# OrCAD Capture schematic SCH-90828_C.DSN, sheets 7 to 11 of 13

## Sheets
7 07 AUDIO: size C; note: SCH-90828 PDF: SPF-90828
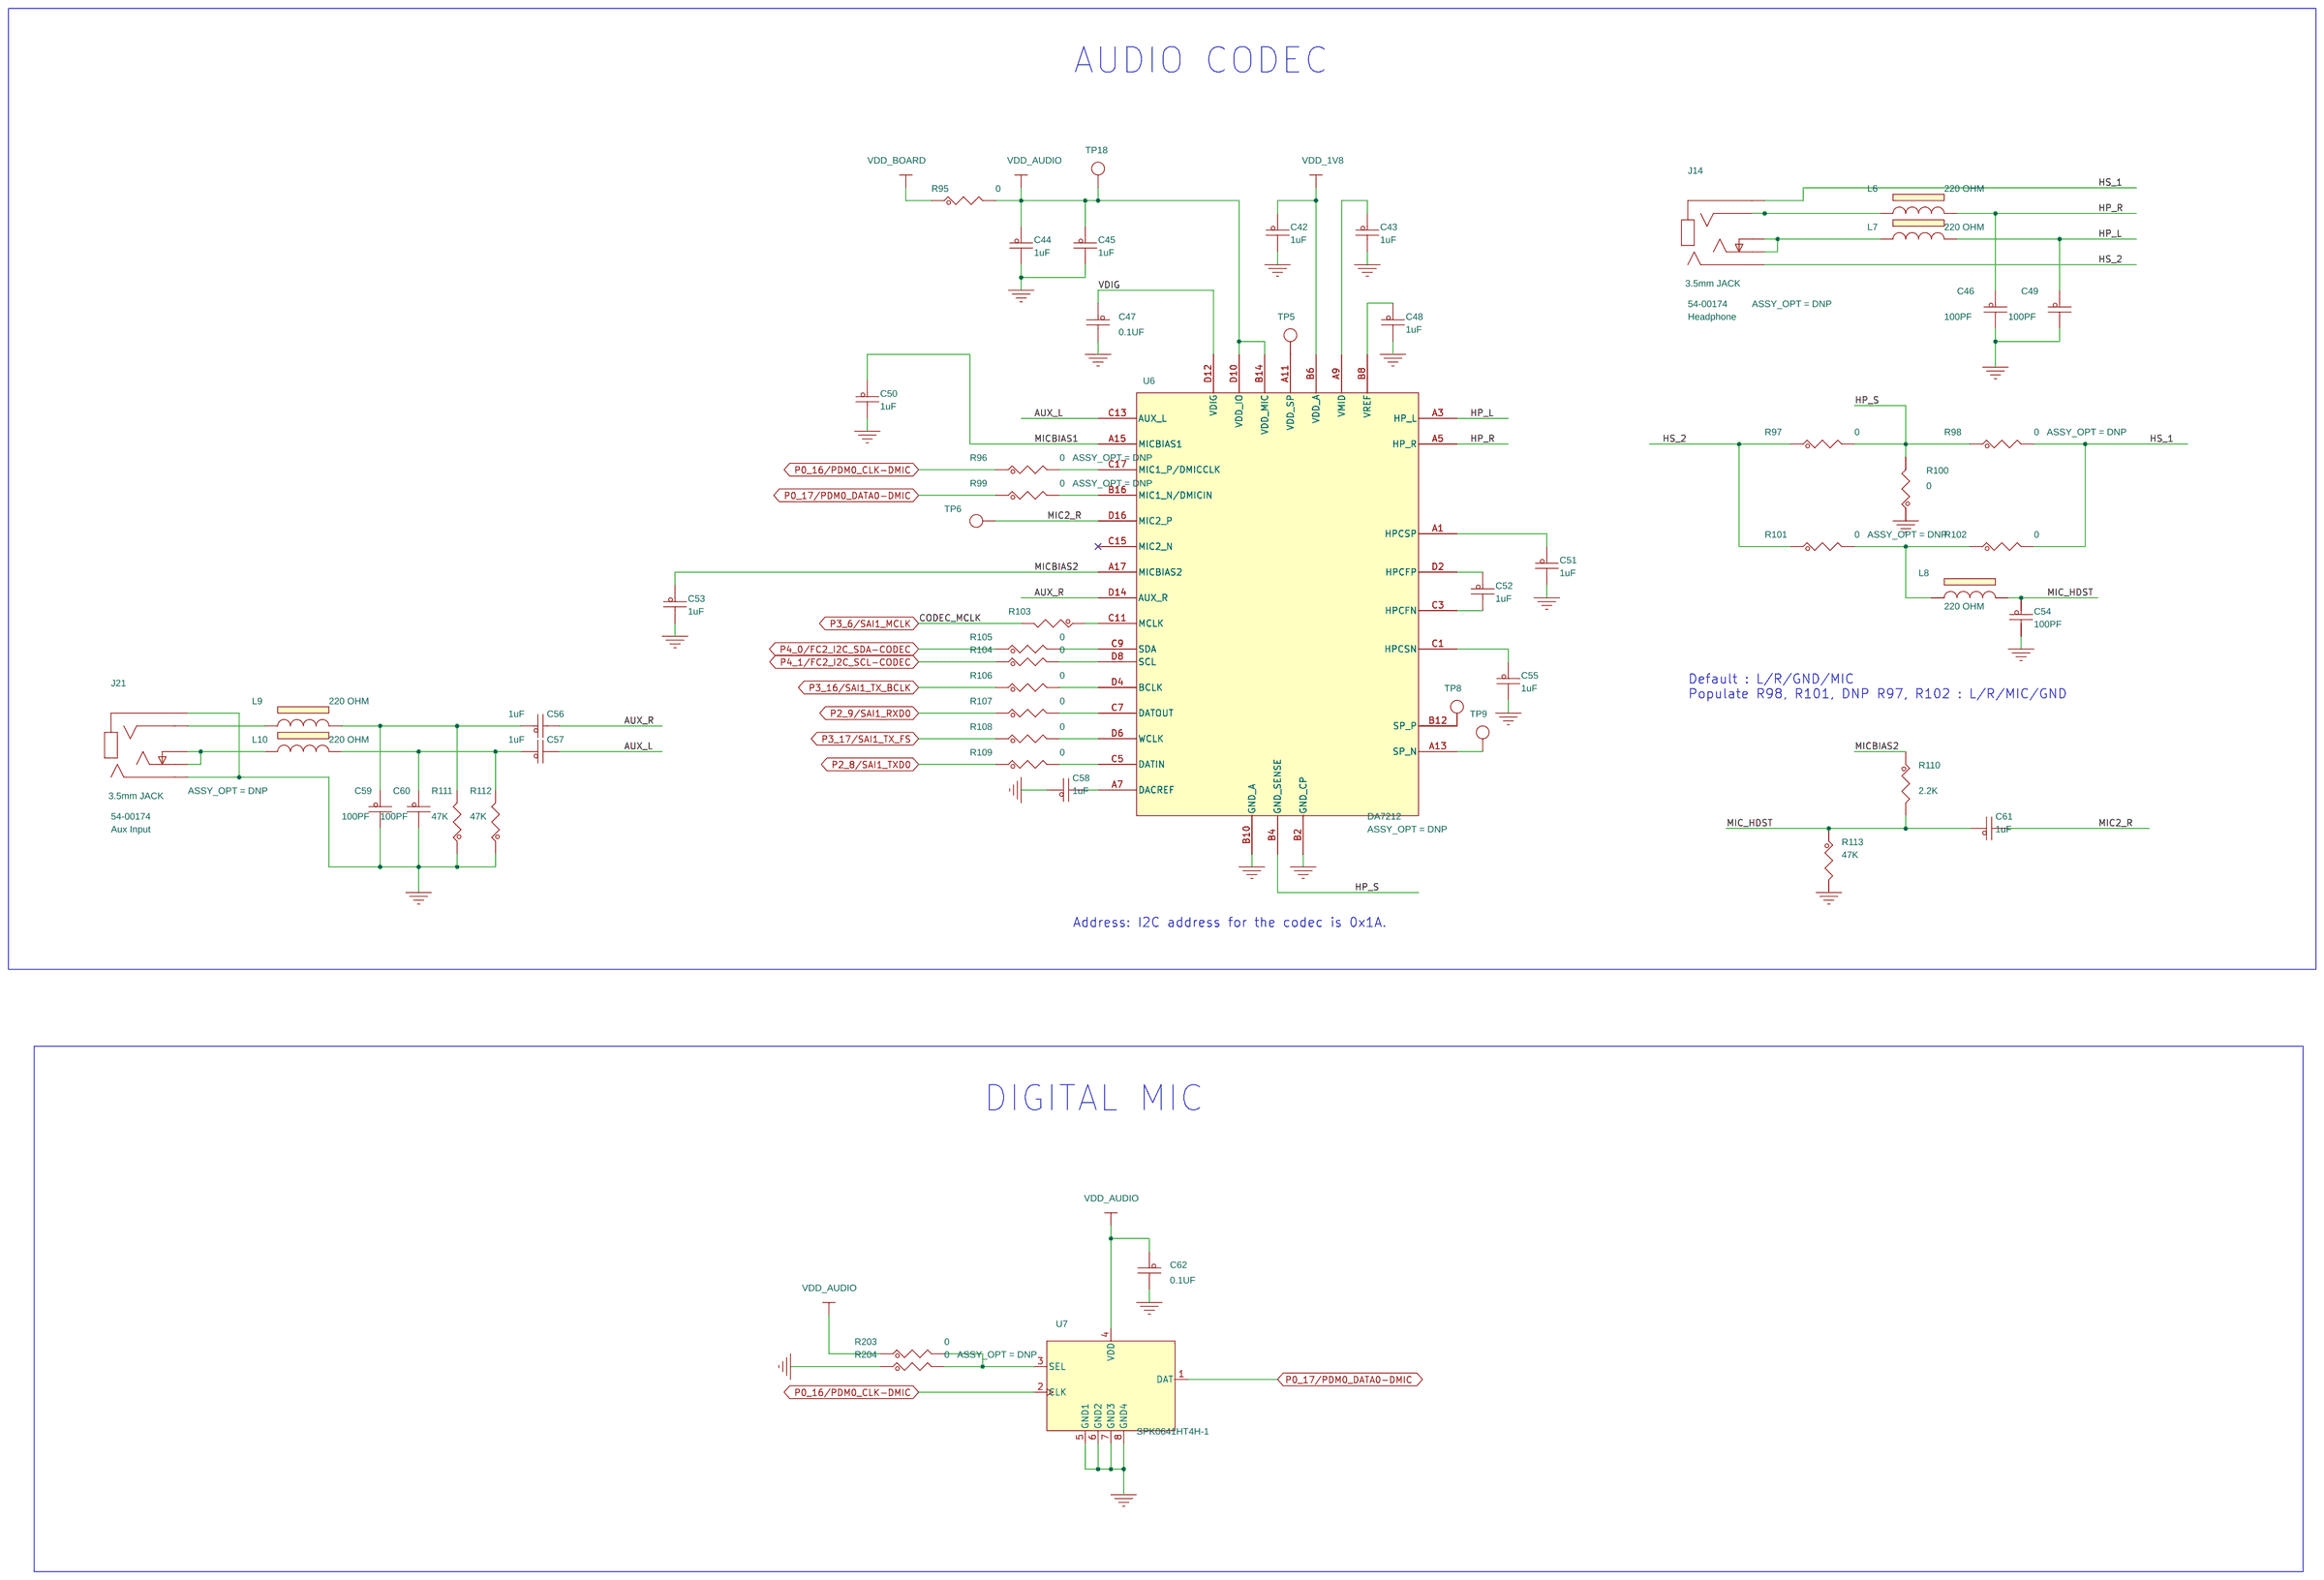
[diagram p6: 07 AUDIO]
8 08 MCU_LINK_USB: size C; note: SCH-90828 PDF: SPF-90828
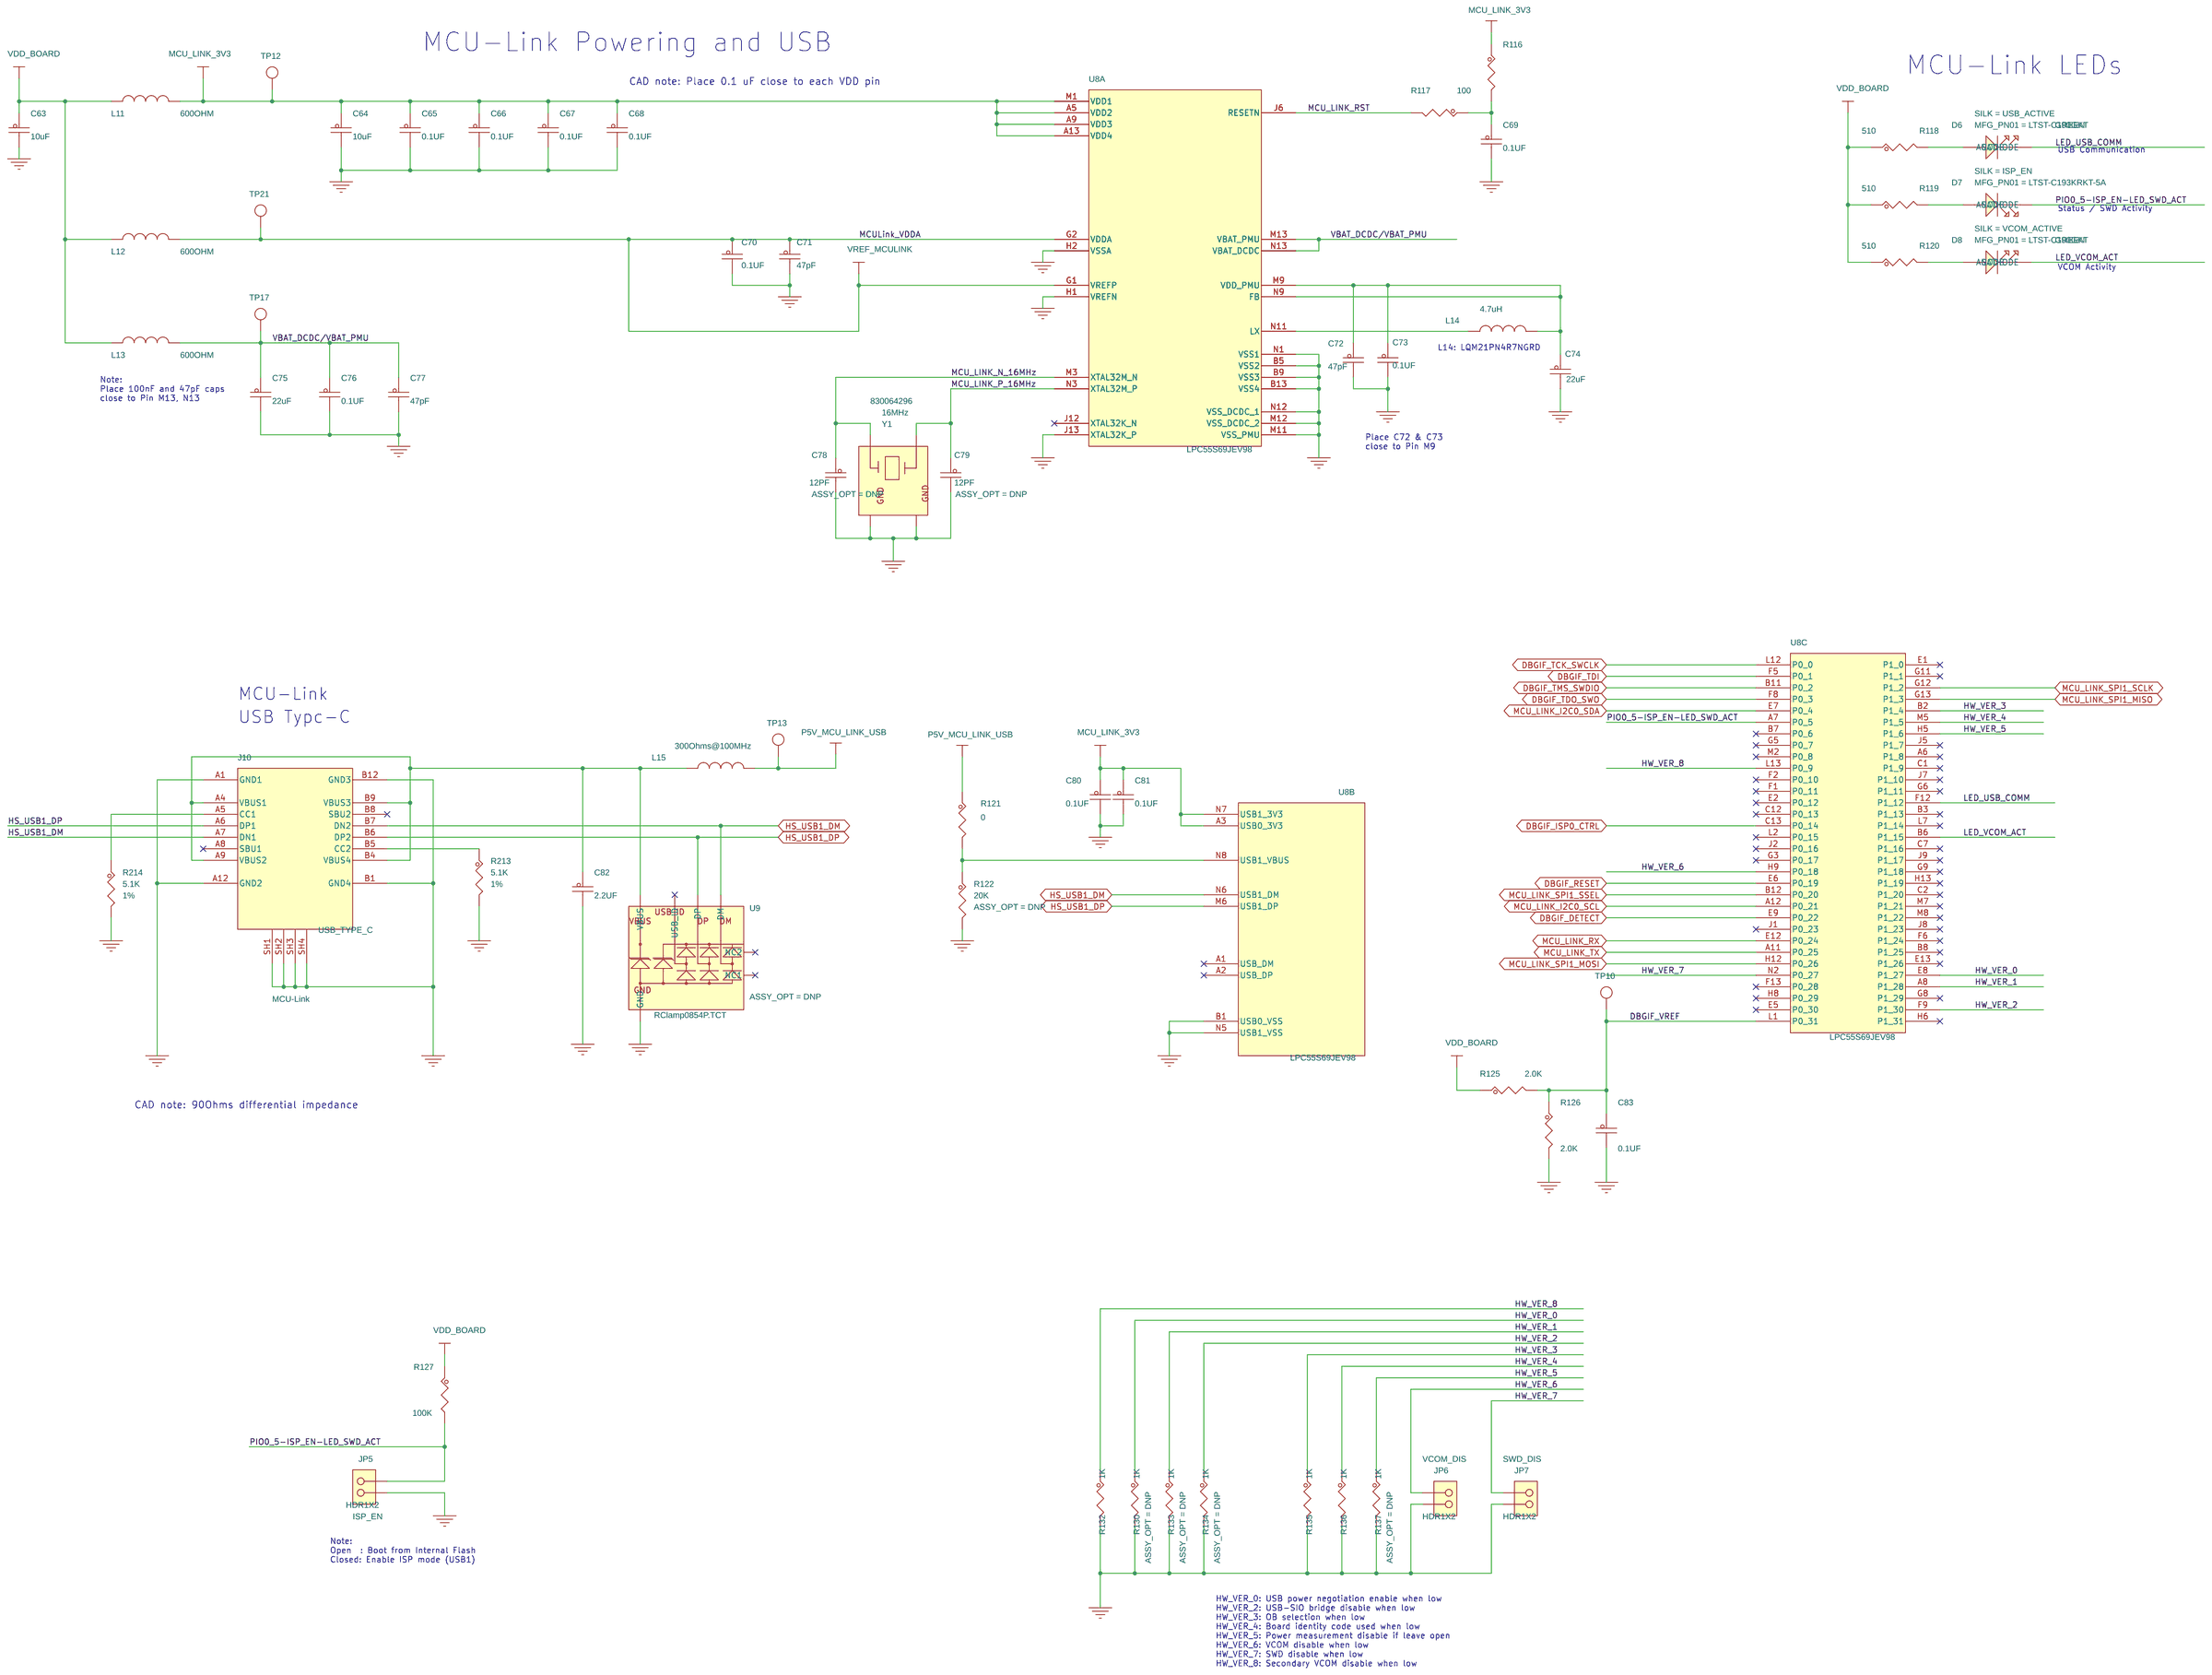
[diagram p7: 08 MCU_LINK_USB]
9 09 MCU_LINK_DEBUG: size C; note: SCH-90828 PDF: SPF-90828
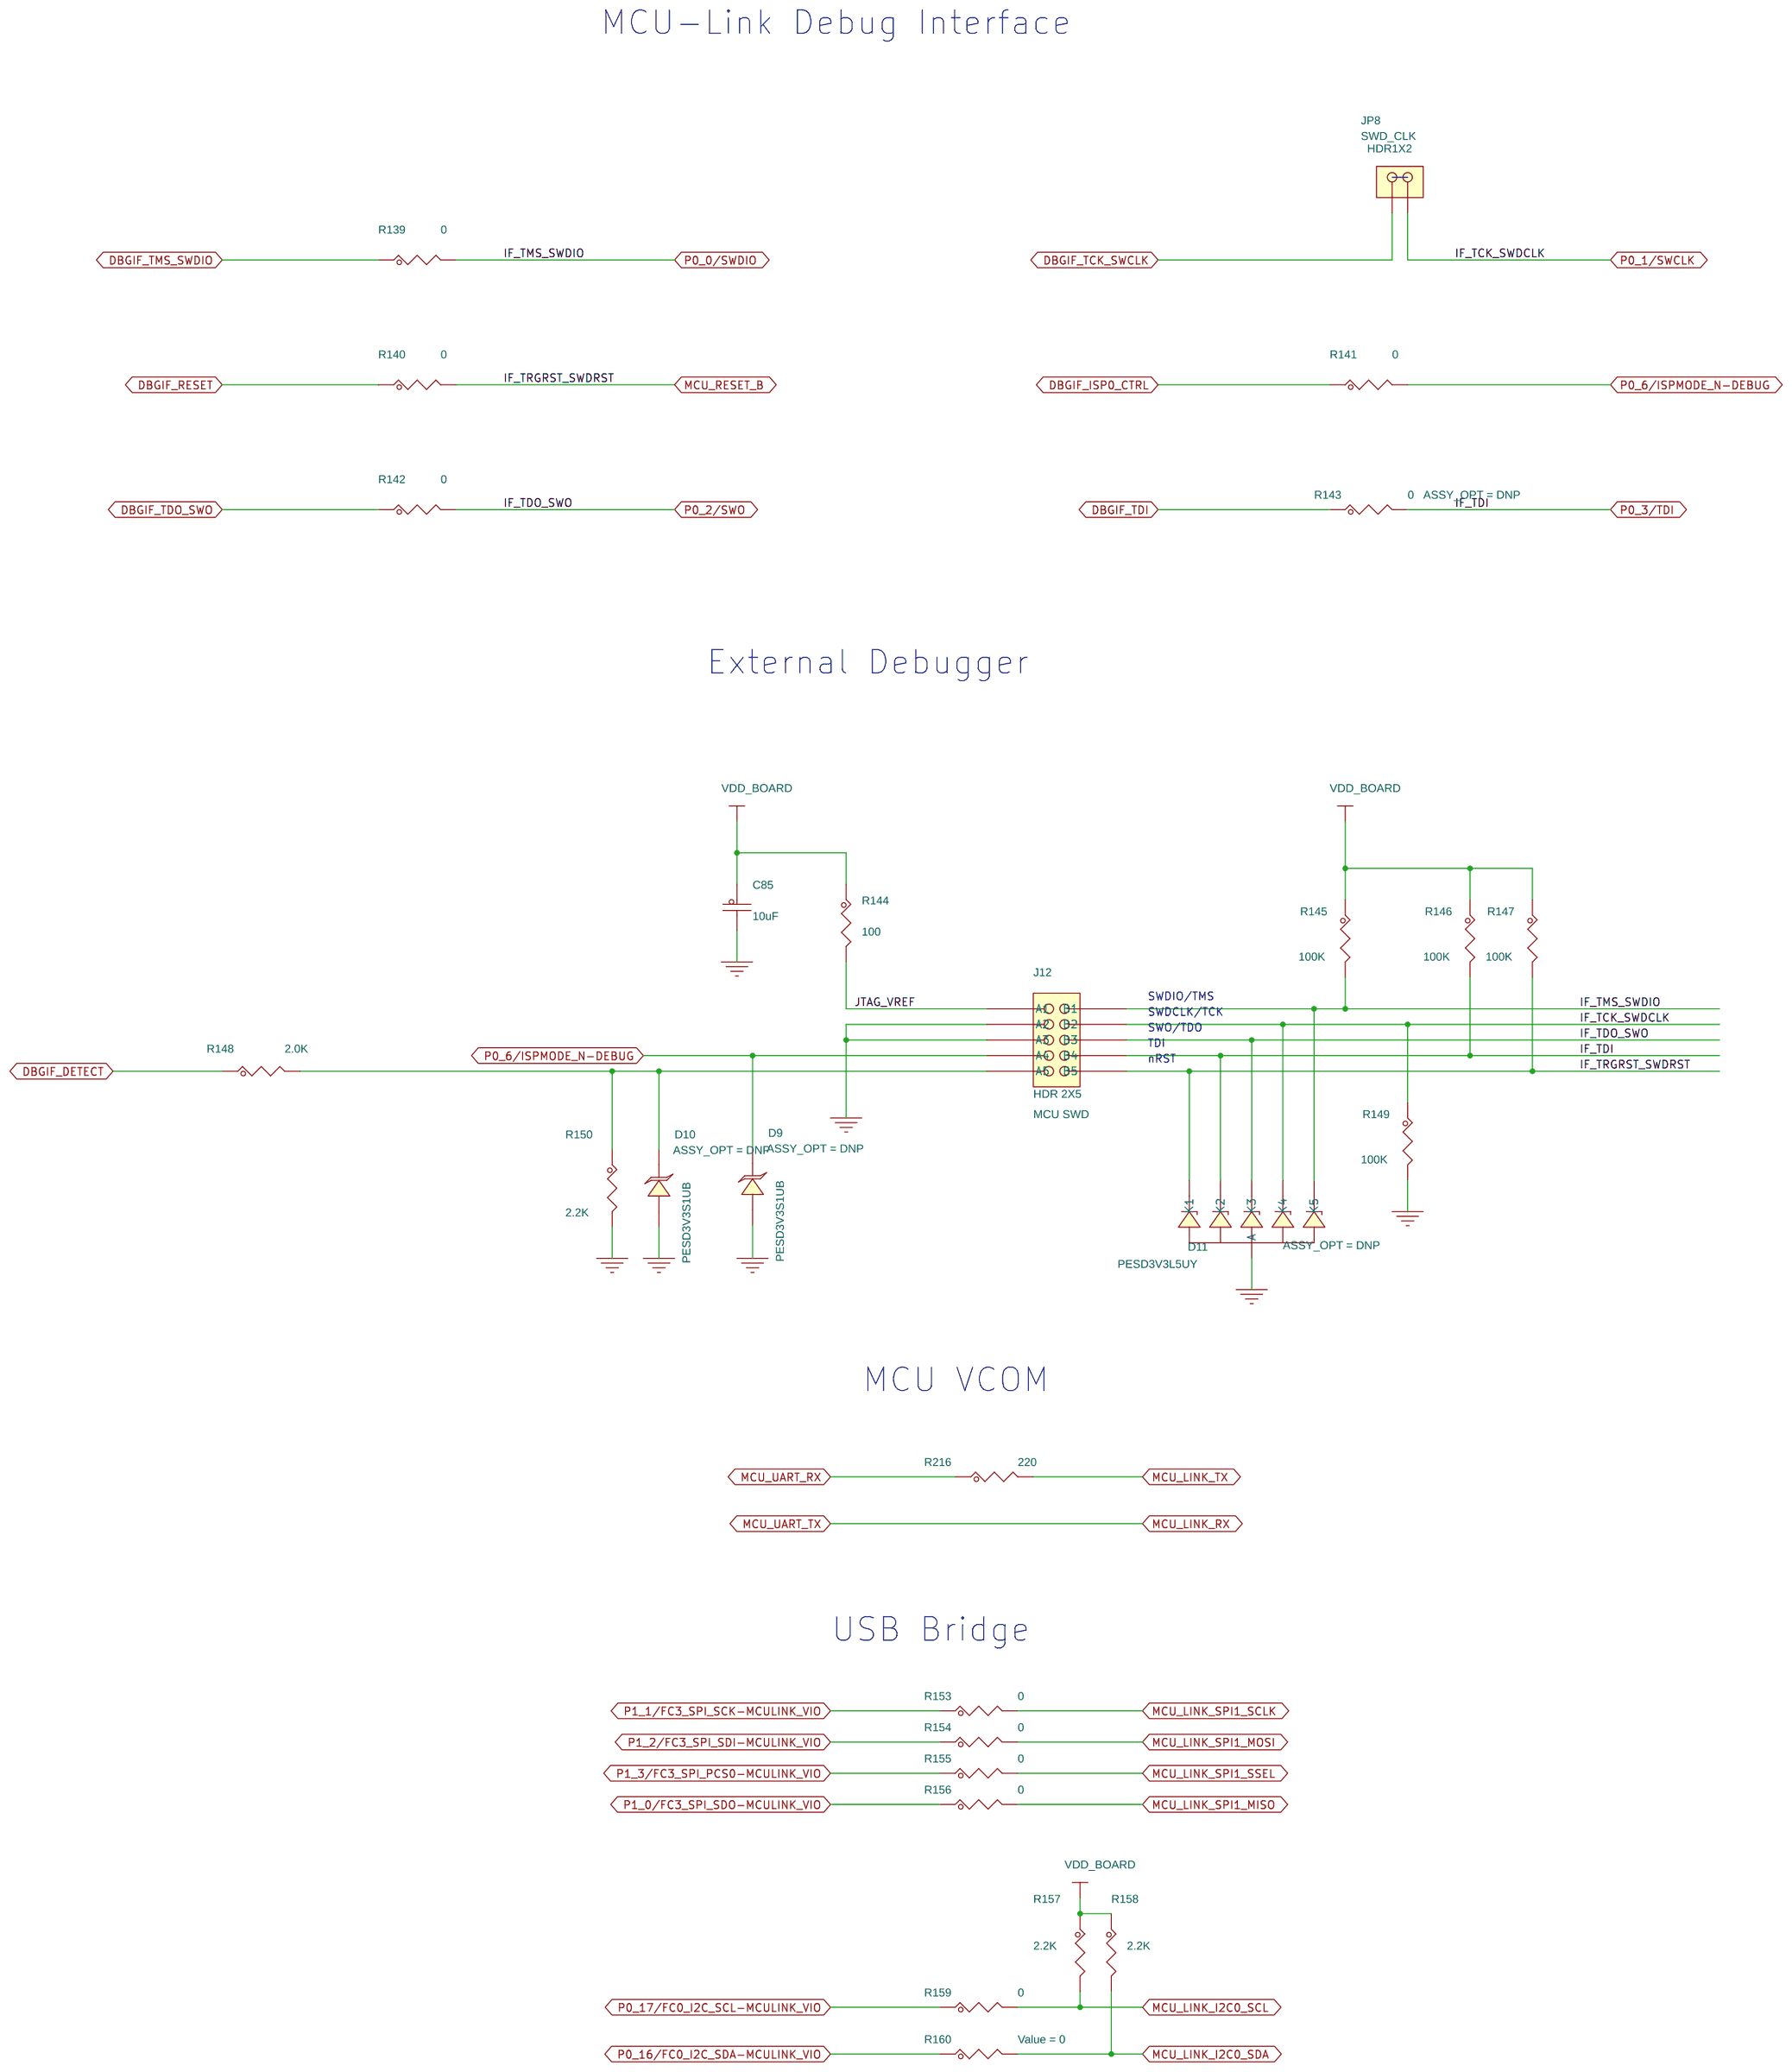
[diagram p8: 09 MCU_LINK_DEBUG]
10 10 CLOCK_RESET_HMI: size C; note: SCH-90828 PDF: SPF-90828
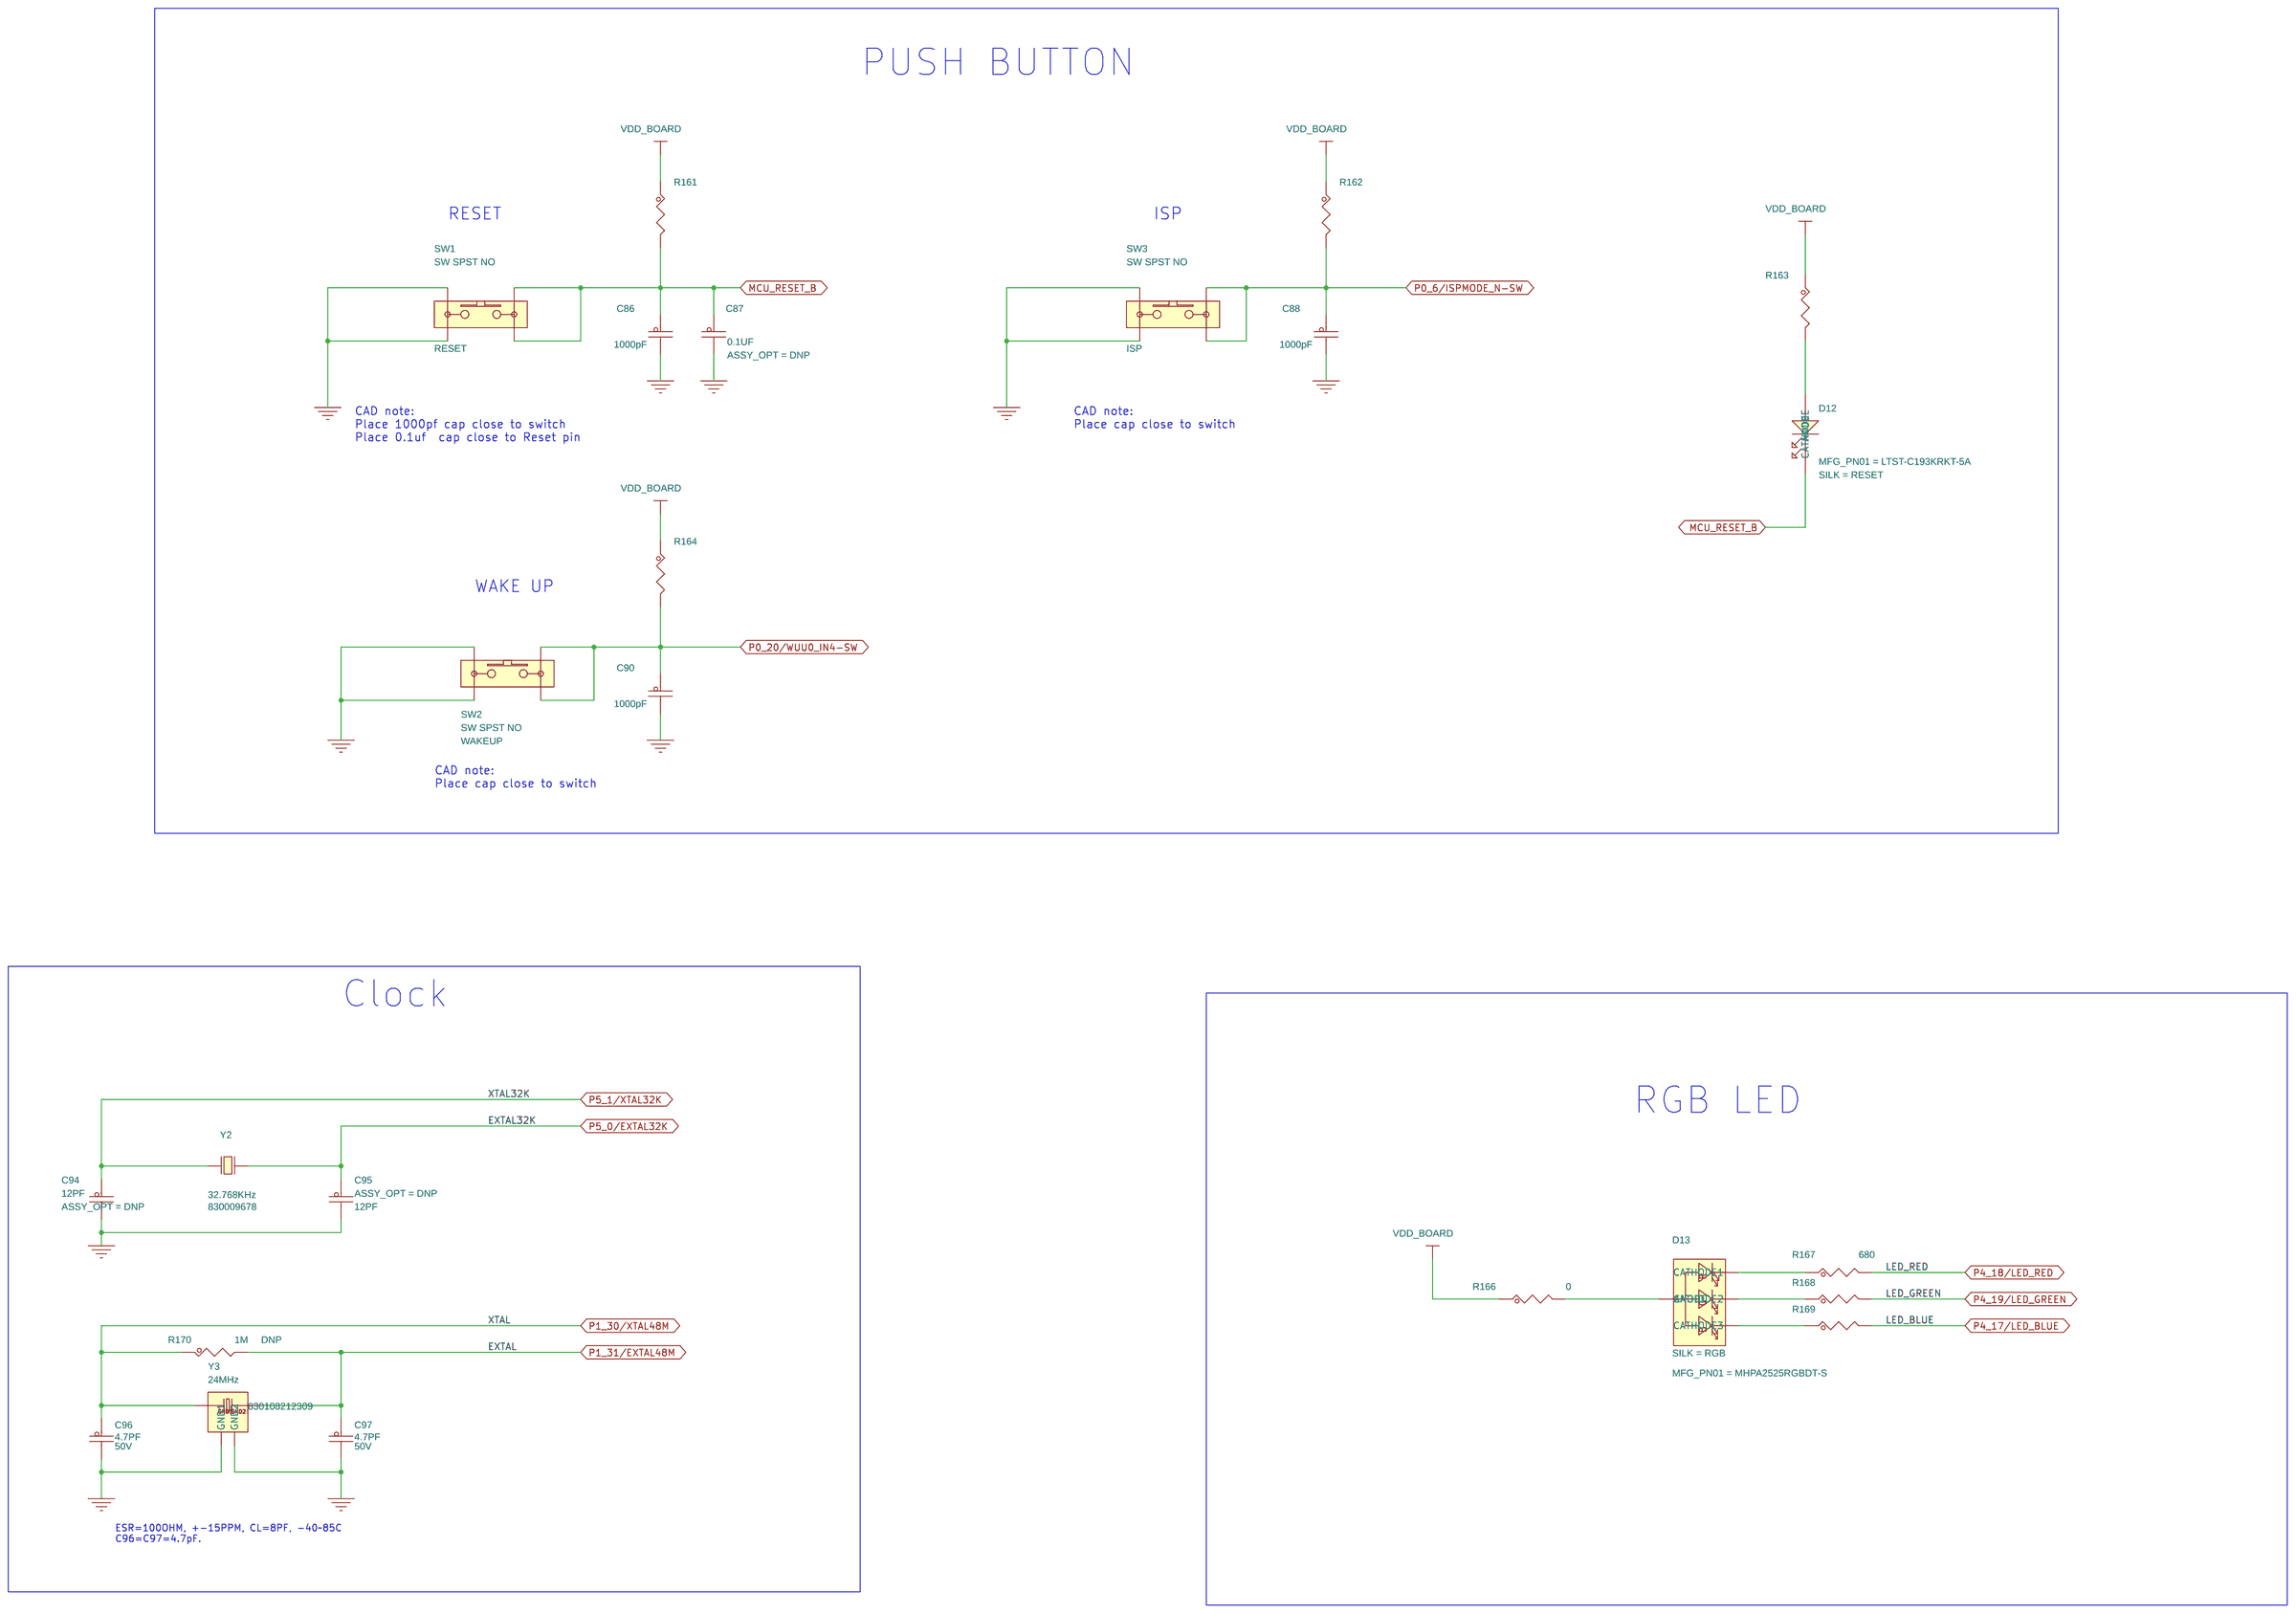
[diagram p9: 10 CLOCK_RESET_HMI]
11 11 SENSOR_CAN_QSPI: size C; note: SCH-90828 PDF: SPF-90828
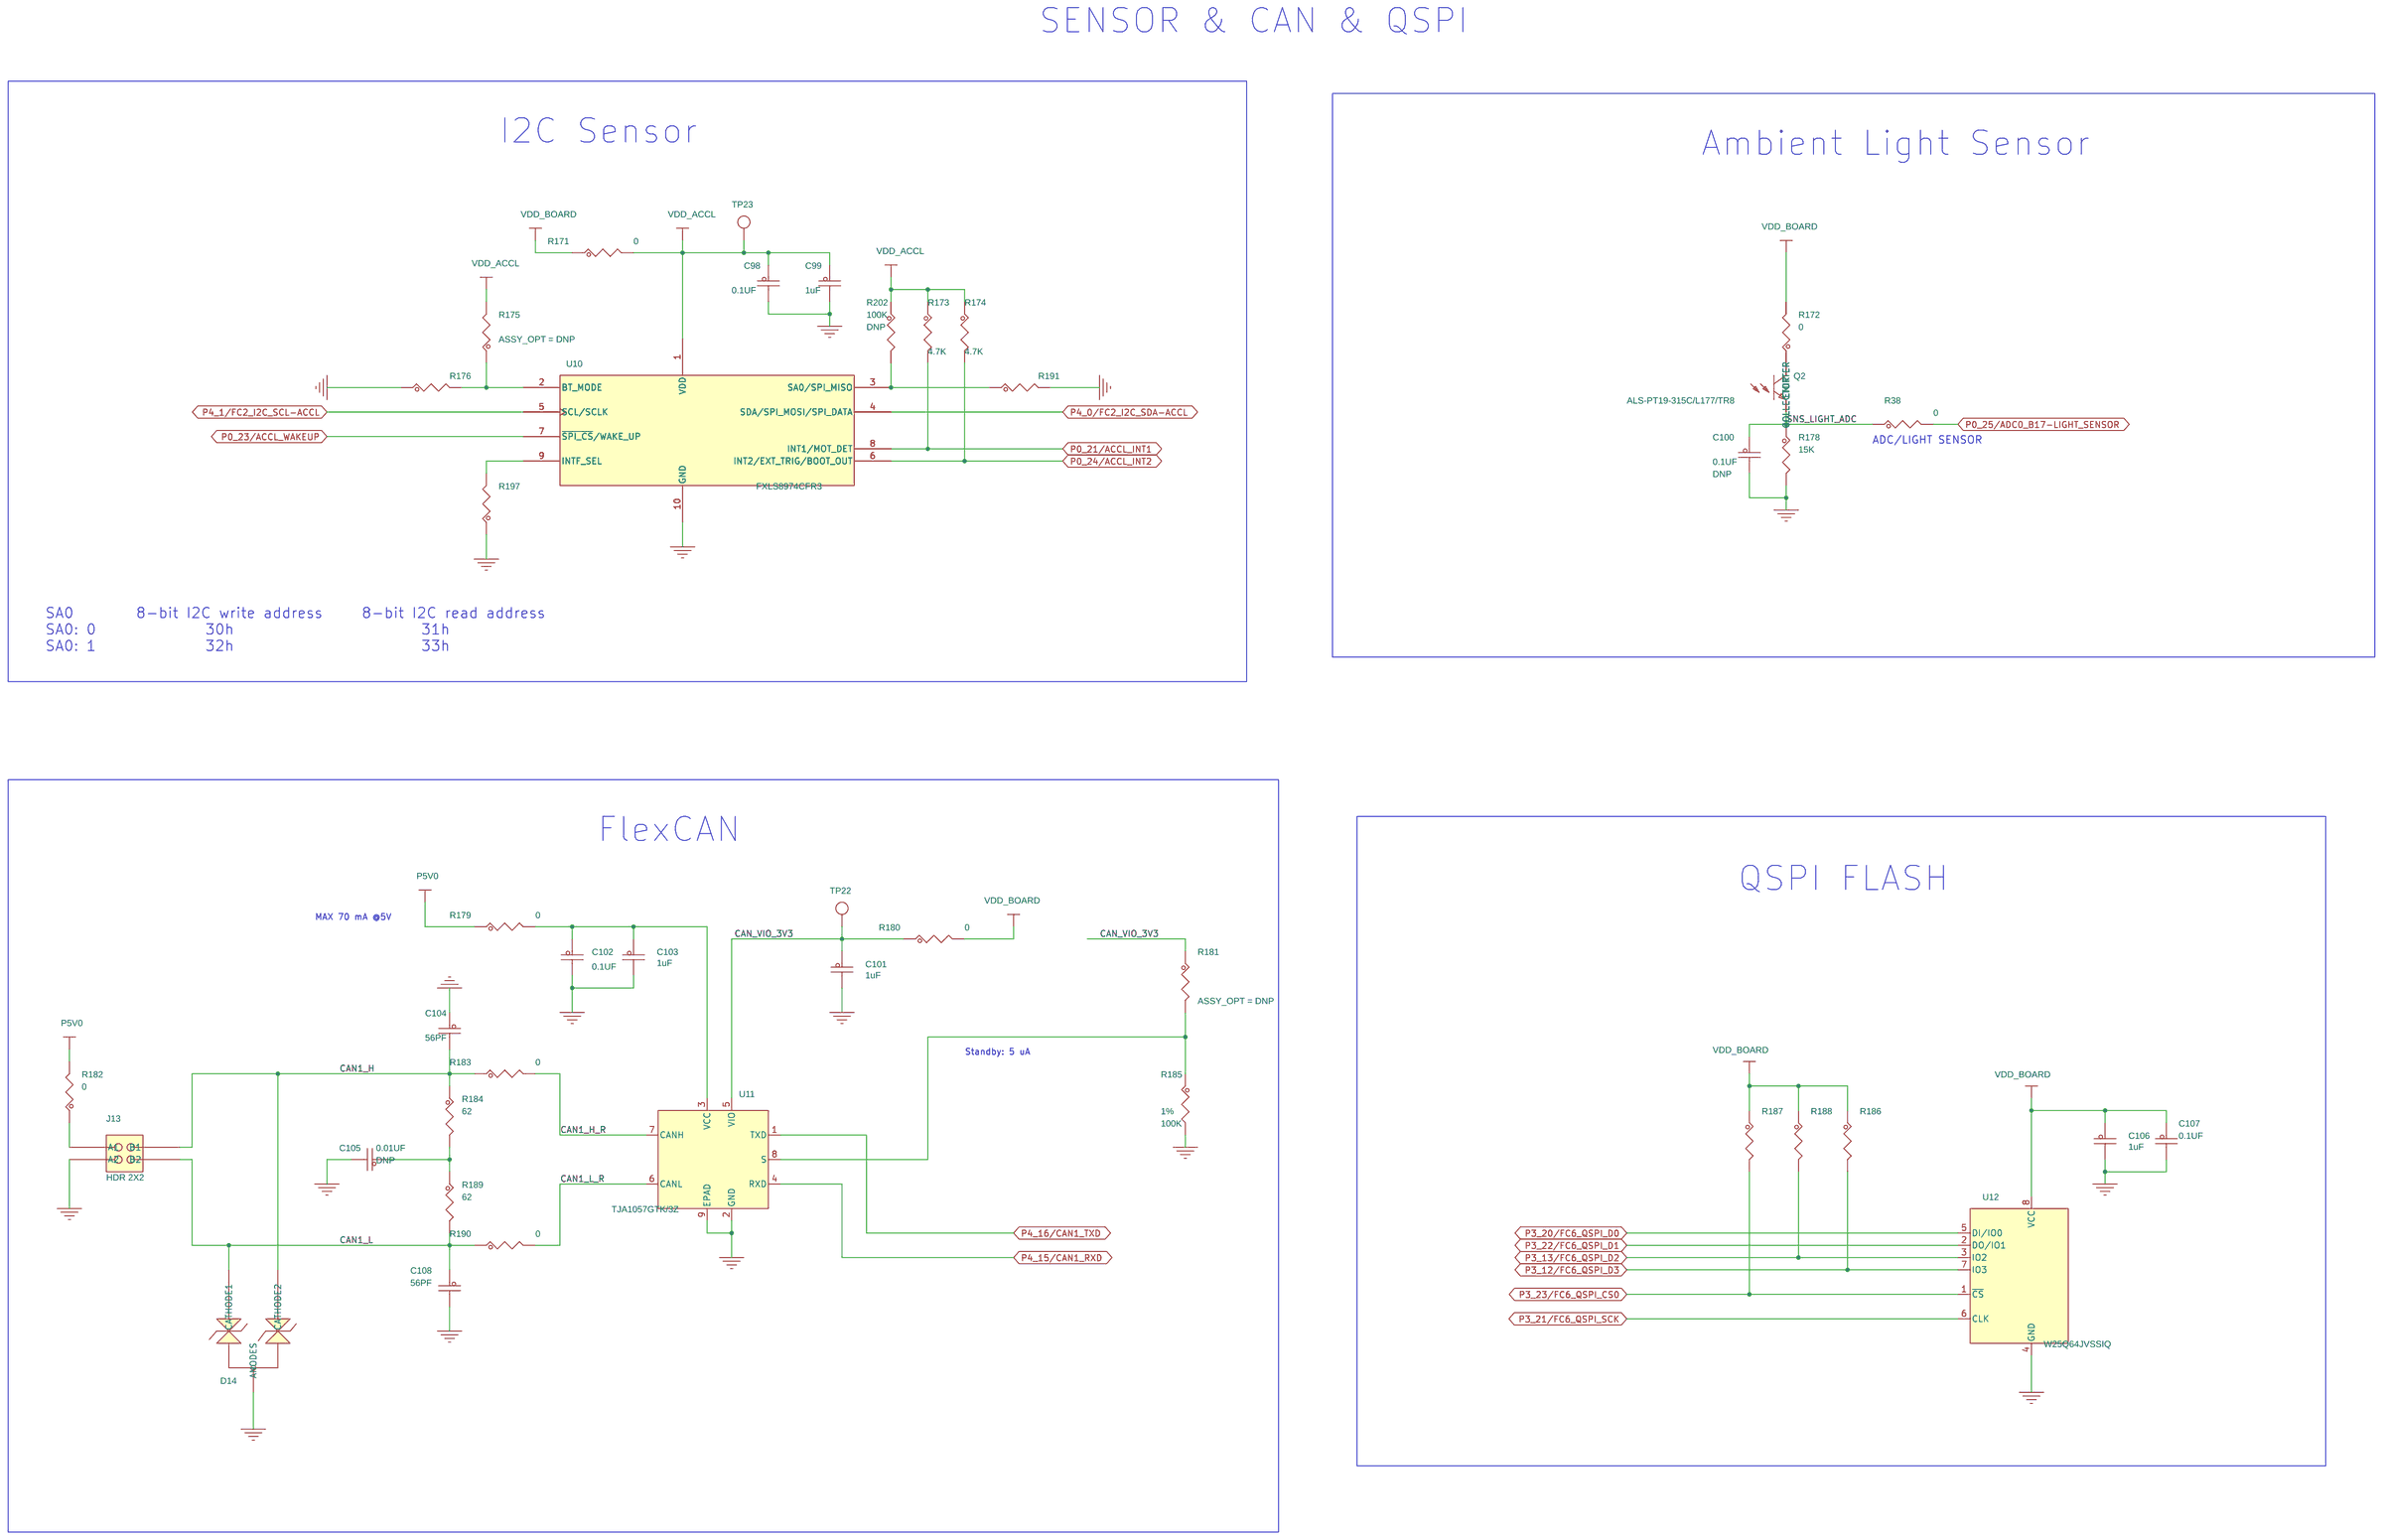
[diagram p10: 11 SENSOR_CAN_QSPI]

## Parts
sheet 07 AUDIO
C42  1uF  [CC0402_25]
C43  1uF  [CC0402_25]
C44  1uF  [CC0402_25]
C45  1uF  [CC0402_25]
C46  100PF  [CC0402_25]
C47  0.1UF  [CC0402_25]
C48  1uF  [CC0402_25]
C49  100PF  [CC0402_25]
C50  1uF  [CC0402_25]
C51  1uF  [CC0402_25]
C52  1uF  [CC0402_25]
C53  1uF  [CC0402_25]
C54  100PF  [CC0402_25]
C55  1uF  [CC0402_25]
C56  1uF  [CC0402_25]
C57  1uF  [CC0402_25]
C58  1uF  [CC0402_25]
C59  100PF  [CC0402_25]
C60  100PF  [CC0402_25]
C61  1uF  [CC0402_25]
C62  0.1UF  [CC0402_25]
J14  3.5mm JACK  [con5_jack_ra_th]
J21  3.5mm JACK  [con5_jack_ra_th]
L6  220 OHM  [IND_0402]
L7  220 OHM  [IND_0402]
L8  220 OHM  [IND_0402]
L9  220 OHM  [IND_0402]
L10  220 OHM  [IND_0402]
R95  0  [RC0402_25]
R96  0  [RC0402_25]
R97  0  [RC0402_25]
R98  0  [RC0402_25]
R99  0  [RC0402_25]
R100  0  [RC0402_25]
R101  0  [RC0402_25]
R102  0  [RC0402_25]
R103  33  [RC0402_25]
R104  0  [RC0402_25]
R105  0  [RC0402_25]
R106  0  [RC0402_25]
R107  0  [RC0402_25]
R108  0  [RC0402_25]
R109  0  [RC0402_25]
R110  2.2K  [RC0402_25]
R111  47K  [RC0402_25]
R112  47K  [RC0402_25]
R113  47K  [RC0402_25]
R203  0  [RC0402_25]
R204  0  [RC0402_25]
TP5  TPAD_040  [TPAD_040]
TP6  TPAD_040  [TPAD_040]
TP8  TPAD_040  [TPAD_040]
TP9  TPAD_040  [TPAD_040]
TP18  TPAD_040  [TPAD_040]
U6  DA7212  [csp34_0p5_4p54x1p66]
U7  SPK0641HT4H-1  [lga8_3p1x4p1mm_spk0641]
sheet 08 MCU_LINK_USB
C63  10uF  [CC0603_OV]
C64  10uF  [CC0603_OV]
C65  0.1UF  [CC0402_25]
C66  0.1UF  [CC0402_25]
C67  0.1UF  [CC0402_25]
C68  0.1UF  [CC0402_25]
C69  0.1UF  [CC0402_25]
C70  0.1UF  [CC0402_25]
C71  47pF  [CC0603_OV]
C72  47pF  [CC0603_OV]
C73  0.1UF  [CC0402_25]
C74  22uF  [CC0603_OV]
C75  22uF  [CC0603_OV]
C76  0.1UF  [CC0402_25]
C77  47pF  [CC0603_OV]
C78  12PF  [0402_CC]
C79  12PF  [0402_CC]
C80  0.1UF  [CC0402_25]
C81  0.1UF  [CC0402_25]
C82  2.2UF  [CC0402_25]
C83  0.1UF  [CC0402_25]
D6  GREEN  [LED_0603]
D7  RED  [LED_0603]
D8  GREEN  [LED_0603]
J10  USB_TYPE_C  [con16_usb_type-c_ra_th]
JP5  HDR1X2  [hdr1x2_5p48x2p69]
JP6  HDR1X2  [hdr1x2_5p48x2p69]
JP7  HDR1X2  [hdr1x2_5p48x2p69]
L11  600OHM  [ind_1p8x1mm_sm]
L12  600OHM  [ind_1p8x1mm_sm]
L13  600OHM  [ind_1p8x1mm_sm]
L14  4.7uH  [IND_0805]
L15  300Ohms@100MHz  [ind_1p8x1mm_sm]
R116  10K  [RC0402_25]
R117  100  [RC0402_25]
R118  510  [RC0402_25]
R119  510  [RC0402_25]
R120  510  [RC0402_25]
R121  0  [RC0402_25]
R122  20K  [RC0402_25]
R125  2.0K  [RC0603_OV]
R126  2.0K  [RC0603_OV]
R127  100K  [RC0402_25]
R130  1K  [rc0402_25]
R132  1K  [rc0402_25]
R133  1K  [rc0402_25]
R134  1K  [rc0402_25]
R135  1K  [rc0402_25]
R136  1K  [rc0402_25]
R137  1K  [rc0402_25]
R213  5.1K  [RC0402_25]
R214  5.1K  [RC0402_25]
TP10  TPAD_040  [TPAD_040]
TP12  TPAD_040  [TPAD_040]
TP13  TPAD_040  [TPAD_040]
TP17  TPAD_040  [TPAD_040]
TP21  TPAD_040  [TPAD_040]
U8  LPC55S69JEV98  [bga98_0p5_7x7]  (sections A,B,C)
U9  RClamp0854P.TCT  [slp1616p6]
Y1  16MHz  [xtal4_3p4x2p7_sm]
sheet 09 MCU_LINK_DEBUG
C85  10uF  [CC0603_OV]
D9  PESD3V3S1UB  [sod523]
D10  PESD3V3S1UB  [sod523]
D11  PESD3V3L5UY  [sot-363_0p65_smt]
J12  HDR 2X5  [hdr_5X2_ftsh_th]
JP8  HDR1X2  [hdr1x2_5p48x2p69]
R139  0  [RC0402_25]
R140  0  [RC0402_25]
R141  0  [RC0402_25]
R142  0  [RC0402_25]
R143  0  [RC0402_25]
R144  100  [RC0402_25]
R145  100K  [RC0402_25]
R146  100K  [RC0402_25]
R147  100K  [RC0402_25]
R148  2.0K  [RC0603_OV]
R149  100K  [RC0402_25]
R150  2.2K  [RC0402_25]
R153  0  [RC0402_25]
R154  0  [RC0402_25]
R155  0  [RC0402_25]
R156  0  [RC0402_25]
R157  2.2K  [RC0402_25]
R158  2.2K  [RC0402_25]
R159  0  [RC0402_25]
R160  0  [RC0402_25]
R216  220  [RC0603_OV]
sheet 10 CLOCK_RESET_HMI
C86  1000pF  [CC0402_25]
C87  0.1UF  [CC0402_25]
C88  1000pF  [CC0402_25]
C90  1000pF  [CC0402_25]
C94  12PF  [CC0402_25]
C95  12PF  [CC0402_25]
C96  4.7PF  [0402_CC]
C97  4.7PF  [0402_CC]
D12  RED  [LED_0603]
D13  RGB  [led4_2p7x2p6_sm]
R161  10K  [RC0402_25]
R162  10K  [RC0402_25]
R163  470  [RC0402_25]
R164  10K  [RC0402_25]
R166  0  [RC0402_25]
R167  680  [RC0603_OV]
R168  470  [RC0402_25]
R169  470  [RC0402_25]
R170  1M  [0402_CC]
SW1  SW SPST NO  [sw4_4p15_4p2x3p2_sm]
SW2  SW SPST NO  [sw4_4p15_4p2x3p2_sm]
SW3  SW SPST NO  [sw4_4p15_4p2x3p2_sm]
Y2  32.768KHz  [XTAL2-3p2x1p5-SM]
Y3  24MHz  [xtal4_2p1x1p7mm_sm]
sheet 11 SENSOR_CAN_QSPI
C98  0.1UF  [CC0402_25]
C99  1uF  [CC0402_25]
C100  0.1UF  [CC0402_25]
C101  1uF  [CC0402_25]
C102  0.1UF  [CC0402_25]
C103  1uF  [CC0402_25]
C104  56PF  [CC0402_25]
C105  0.01UF  [CC0402_25]
C106  1uF  [CC0402_25]
C107  0.1UF  [CC0402_25]
C108  56PF  [CC0402_25]
D14  NUP2105L  [sot-23]
J13  HDR 2X2  [hdr202_100_th]
Q2  ALS-PT19-315C/L177/TR8  [phtrans_1p9x1]
R38  0  [RC0402_25]
R171  0  [RC0402_25]
R172  0  [RC0402_25]
R173  4.7K  [RC0402_25]
R174  4.7K  [RC0402_25]
R175  10K  [RC0402_25]
R176  10K  [RC0402_25]
R178  15K  [RC0402_25]
R179  0  [RC0402_25]
R180  0  [RC0402_25]
R181  10K  [RC0402_25]
R182  0  [RC0402_25]
R183  0  [RC0402_25]
R184  62  [RC0805_OV]
R185  100K  [RC0402_25]
R186  10K  [RC0402_25]
R187  10K  [RC0402_25]
R188  10K  [RC0402_25]
R189  62  [RC0805_OV]
R190  0  [RC0402_25]
R191  10K  [RC0402_25]
R197  10K  [RC0402_25]
R202  100K  [RC0402_25]
TP22  TPAD_040  [TPAD_040]
TP23  TPAD_040  [TPAD_040]
U10  FXLS8974CFR3  [DFN_10_0P4_2X2]
U11  TJA1057GTK/3Z  [son8_0p65_3p15x3p15]
U12  W25Q64JVSSIQ  [so8_w]

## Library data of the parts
C42-C45 C48 C50-C53 C55-C58 C61 C99 C101 C103 C106 = CAP_NP: CAP CER 1uF 10V 10% X7S 0402; AGILE_PN: 150-80357; CAD_APPROVED: Yes; FPLIST: CC0402_25,CC0402_HD,0402_CC,capc0402_l; HEIGHT: 0.6; MFG_NAME01: MURATA; MFG_PN01: GRM155C71A105KE11D; Package Size: 0402; ROHS: Yes; Rated Voltage: 10V; Temp Range: -55C to +125C; Tolerance: 10%
C46 C49 C54 C59 C60 = CAP_NP: CAP CER 100pF 16V 10% X7R 0402; AGILE_PN: 150-79188; CAD_APPROVED: Yes; FPLIST: CC0402_25,CC0402_HD,0402_CC; HEIGHT: 0.56; MFG_NAME01: AVX; MFG_PN01: 0402YC101KAT2A; Package Size: 0402; Package Type: 7" Reel; ROHS: Yes; Rated Voltage: 16V; TOL: 10%; Temp Range: -55C to +125C; Tolerance: 10%; VOLTAGE: 16V
C47 C62 C65-C70 C73 C76 C80 C81 C83 C98 C102 = CAP_NP: CAP CER 0.1UF 16V 10% X7R 0402; 3D_Mechanical_Footprint_File: http://fcl.am.freescale.net/ALLEGRO/step/cc0402_25.STEP; AGILE_PN: 150-75182; CAD_APPROVED: Yes; FPLIST: CC0402_25,CC0402_HD,0402_CC,CAPC0402_L; HEIGHT: 0.635; MFG_NAME01: Samsung Electro-Mechanics; MFG_PN01: CL05B104KO5NNNC; ROHS: Yes; Rated Voltage: 16V; Temp Range: -55C to +125C; Tolerance: 10%; VOLTAGE: 16V
J14 = 3.5MM_PHONE_JACK: CON 5 MONO AUDIO JACK 3.5MM SKT TH RA 256H AG 79L; 3D_Mechanical_Footprint_File: http://fcl.am.freescale.net/ALLEGRO/step/con5_jack_ra_th.STEP; AGILE_PN: 210-83388; ASSY_OPT: DNP; CAD_APPROVED: Yes; HEIGHT: 6.5; MFG_NAME01: Tensility International Corp; MFG_PN01: 54-00174; Package Size: 12.7x7.5MM; Package Type: THRU-HOLE RA; ROHS: Yes; SILK: Headphone; Temp Range: -40 to 105°C
J21 = 3.5MM_PHONE_JACK: CON 5 MONO AUDIO JACK 3.5MM SKT TH RA 256H AG 79L; 3D_Mechanical_Footprint_File: http://fcl.am.freescale.net/ALLEGRO/step/con5_jack_ra_th.STEP; AGILE_PN: 210-83388; ASSY_OPT: DNP; CAD_APPROVED: Yes; HEIGHT: 6.5; MFG_NAME01: Tensility International Corp; MFG_PN01: 54-00174; Package Size: 12.7x7.5MM; Package Type: THRU-HOLE RA; ROHS: Yes; SILK: Aux Input; Temp Range: -40 to 105°C
L6-L10 = INDUCTOR_FERRITE: IND FER BEAD 220 OHM@100MHZ 0.3A 25% 0.35 OHM 0402; AGILE_PN: 180-77772; CAD_APPROVED: Yes; FPLIST: IND_0402,0402_CC; HEIGHT: 0.55; MFG_NAME01: MURATA; MFG_PN01: BLM15AG221SN1D; Package Size: 0402; ROHS: Yes
R38 R95 R97 R100 R102 R104-R109 R121 R139-R142 R153-R156 R159 R160 R166 R171 R172 R179 R180 R182 R183 R190 R203 = RES: RES MF ZERO OHM 1/10W -- 0402; AGILE_PN: 470-79965; CAD_APPROVED: Yes; FPLIST: RC0402_25,RC0402_HD,RC0402_X2,0402_CC,RC0402_X3; HEIGHT: 0.4; MFG_NAME01: PANASONIC; MFG_PN01: ERJ-2GE0R00X; ROHS: Yes; Temp Range: –55 °C to +155 °C
R96 R98 R99 R101 R143 R204 = RES: RES MF ZERO OHM 1/10W -- 0402; AGILE_PN: 470-79965; ASSY_OPT: DNP; CAD_APPROVED: Yes; FPLIST: RC0402_25,RC0402_HD,RC0402_X2,0402_CC,RC0402_X3; HEIGHT: 0.4; MFG_NAME01: PANASONIC; MFG_PN01: ERJ-2GE0R00X; ROHS: Yes; Temp Range: –55 °C to +155 °C
R103 = RES: RES MF 33.0 OHM 1/16W 1% 0402; AGILE_PN: 470-75790; CAD_APPROVED: Yes; FPLIST: RC0402_25,RC0402_HD,RC0402_X2,0402_CC; HEIGHT: 0.4; MFG_NAME01: THYE MING TECH CO LTD; MFG_PN01: CR-02FL6---33R; PRIORITY_PN: 006-00556; ROHS: Yes; SIGNAL_MODEL: DEFAULT_RESISTOR_33.000000OHM_2_1; TOL: 1%; Tolerance: 1%
R110 R150 R157 R158 = RES: RES MF 2.2K 1/16W 1% 0402; 3D_Mechanical_Footprint_File: http://fcl.am.freescale.net/ALLEGRO/step/rc0402_25.STEP; AGILE_PN: 470-83213; CAD_APPROVED: yes; FPLIST: RC0402_25,RC0402_HD,0402_CC; HEIGHT: 0.4; MFG_NAME01: Bourns Inc.; MFG_PN01: CR0402-FX-2201GLF; ROHS: Yes; Temp Range: -55 °C to +155 °C; Temp_Range: -55C to +155C
R111 R112 = RES: RES MF 47K  1/16W 1% 0402; AGILE_PN: 470-31023; CAD_APPROVED: Yes; FPLIST: RC0402_25,RC0402_HD,RC0402_X2,0402_CC; HEIGHT: 0.40; MFG_NAME01: VISHAY; MFG_PN01: CRCW040247K0FKEDC; ROHS: Yes; Temp Range: –55 °C to +155 °C; Temp_Range: -55&#8451; to 155&#8451;; Tolerance: 1%
R113 = RES: RES MF 47K  1/16W 1% 0402; AGILE_PN: 470-31023; CAD_APPROVED: Yes; FPLIST: RC0402_25,RC0402_HD,0402_CC; HEIGHT: 0.40; MFG_NAME01: VISHAY; MFG_PN01: CRCW040247K0FKEDC; ROHS: Yes; TOL: 1%; Temp Range: –55 °C to +155 °C; Temp_Range: –55 °C to +155 °C; Tolerance: 1%
TP5 TP6 TP8-TP10 TP12 TP13 TP17 TP18 TP21-TP23 = TestLoop: TEST POINT PAD 40MIL DIA SMT, NO PART TO ORDER; AGILE_PN: 211-76643; CAD_APPROVED: Yes; HEIGHT: 0.1; MFG_NAME01: NOTACOMPONENT; MFG_PN01: NOTACOMPONENT; ROHS: Yes
U6 = DA7212_CSP_34P: IC AUDIO CODEC 1.6-2.65V CSP34; 3D_Mechanical_Footprint_File: http://fcl.am.freescale.net/ALLEGRO/step/csp34_0p5_4p54x1p66.STEP; AGILE_PN: 312-81524; ASSY_OPT: DNP; CAD_APPROVED: Yes; HEIGHT: 0.551; MFG_NAME01: DIALOG SEMICONDUCTOR; MFG_PN01: DA7212-01UM2; ROHS: Yes; VOLTAGE: 1.6-2.65V
U7 = SPK0641HT4H_8P: IC MIC MEMS PDM DIGITAL SISONIC -26DB 1.6-3.6V LGA8; 3D_Mechanical_Footprint_File: http://fcl.am.freescale.net/ALLEGRO/step/lga8_3p1x4p1mm_spk0641.STEP; AGILE_PN: 510-78247; CAD_APPROVED: Yes; HEIGHT: 1.1; MFG_NAME01: KNOWLES ACOUSTICS; ROHS: Yes
C63 C64 C85 = CAP_NP: CAP CER 10uF 25V 10% X5R 0603; 3D_Mechanical_Footprint_File: http://fcl.am.freescale.net/ALLEGRO/step/cc0603_ov.STEP; AGILE_PN: 150-79569; CAD_APPROVED: Yes; HEIGHT: 1; MFG_NAME01: SANYEAR; MFG_PN01: C0603X5R106K250NT; Package Size: 0603 [1608 Metric]; Package Type: SMD/SMT; ROHS: Yes; Rated Voltage: 25V; Tolerance: 10%
C71 C72 C77 = CAP_NP: CAP CER 47pF 50V 5% C0G AEC-Q200 0603; AGILE_PN: 150-79357; CAD_APPROVED: Yes; FPLIST: CC0603_OV,CC0603,0603_CC; HEIGHT: 0.9; MFG_NAME01: TDK; MFG_PN01: CGA3E2C0G1H470J080AA; Package Size: 0603; Package Type: Reel; ROHS: Yes; Rated Voltage: 50V; Temp Range: -55C to +125C; Tolerance: 5%; VOLTAGE: 50V
C74 C75 = CAP_NP: CAP CER 22uF 10V 20% X5R 0603; AGILE_PN: 150-79530; CAD_APPROVED: Yes; FPLIST: CC0603_OV,CC0603; HEIGHT: 1; MFG_NAME01: SAMSUNG; MFG_PN01: CL10A226MP7LUNC; Package Size: 0603; ROHS: Yes; Rated Voltage: 10V; Temp Range: -55C to +85C; Tolerance: 20%; VOLTAGE: 10V
C78 C79 = CAP_NP: CAP CER 12PF 25V 5% C0G 0402; AGILE_PN: 150-30180; ASSY_OPT: DNP; CAD_APPROVED: Yes; FPLIST: CC0402_25,CC0402_HD,0402_CC; HEIGHT: 0.55; MFG_NAME01: KEMET; MFG_PN01: C0402C120J3GAC7867; ROHS: Yes; Rated Voltage: 25V; Temp Range: -55C to +125C; Tolerance: 5%
C82 = CAP_NP: CAP CER 2.2UF 10V 20% X5R 0402; 3D_Mechanical_Footprint_File: http://fcl.am.freescale.net/ALLEGRO/step/cc0402_25.STEP; AGILE_PN: 150-79665; CAD_APPROVED: Yes; FPLIST: CC0402_25,CC0402_HD,0402_CC,capc0402_l; HEIGHT: 0.55; MFG_NAME01: KEMET; MFG_PN01: C0402C104M3PAC7867; ROHS: Yes; Rated Voltage: 10V; Temp Range: -55C to +85C; Tolerance: 20%; VOLTAGE: 10V
D6 = LED: LED GREEN GAP ON GAP SM 0603; AGILE_PN: 370-75088; CAD_APPROVED: Yes; HEIGHT: 0.80; MFG_NAME01: LITE ON; MFG_PN01: LTST-C190GKT; SILK: USB_ACTIVE
D7 = LED: LED RED SGL 20MA 0603; AGILE_PN: 370-76632; CAD_APPROVED: Yes; HEIGHT: 0.45; MFG_NAME01: LITE ON; MFG_PN01: LTST-C193KRKT-5A; ROHS: Yes; SILK: ISP_EN
D8 = LED: LED GREEN GAP ON GAP SM 0603; AGILE_PN: 370-75088; CAD_APPROVED: Yes; HEIGHT: 0.80; MFG_NAME01: LITE ON; MFG_PN01: LTST-C190GKT; SILK: VCOM_ACTIVE
J10 = USB16_TYPEC_4SH: CON 2X8 USB2.0_TYPE_C RCPT 0.85MM 144H AU 63L; AGILE_PN: 210-82931; CAD_APPROVED: Yes; HEIGHT: 3.66; MFG_NAME01: GCT; MFG_PN01: USB4085-GF-A; Package Type: Through Hole, Right Angle; ROHS: Yes; SILK: MCU-Link; Temp Range: -40 °C to +85 °C
JP5 = CONN_HDR_2X1: HDR 1X2 TH 100MIL SP 342H AU 118L; 3D_Mechanical_Footprint_File: http://fcl.am.freescale.net/ALLEGRO/step/hdr1x2_5p48x2p69.STEP; AGILE_PN: 210-80468; CAD_APPROVED: Yes; HEIGHT: 8.69; JUMPER(DEFAULT): OPEN; MFG_NAME01: WURTH ELEKTRONIK EISOS GMBH & CO. KG (ELECTRONIC & ELECTROMEHANICAL COMP); MFG_PN01: 61300211121; Package Type: TH; ROHS: Yes; SILK: ISP_EN; Temp Range: -40°C to 105°C
JP6 = CONN_HDR_2X1: HDR 1X2 TH 100MIL SP 342H AU 118L; 3D_Mechanical_Footprint_File: http://fcl.am.freescale.net/ALLEGRO/step/hdr1x2_5p48x2p69.STEP; AGILE_PN: 210-80468; CAD_APPROVED: Yes; HEIGHT: 8.69; JUMPER(DEFAULT): OPEN; MFG_NAME01: WURTH ELEKTRONIK EISOS GMBH & CO. KG (ELECTRONIC & ELECTROMEHANICAL COMP); MFG_PN01: 61300211121; Package Type: TH; ROHS: Yes; SILK: VCOM_DIS; Temp Range: -40°C to 105°C
JP7 = CONN_HDR_2X1: HDR 1X2 TH 100MIL SP 342H AU 118L; 3D_Mechanical_Footprint_File: http://fcl.am.freescale.net/ALLEGRO/step/hdr1x2_5p48x2p69.STEP; AGILE_PN: 210-80468; CAD_APPROVED: Yes; HEIGHT: 8.69; JUMPER(DEFAULT): OPEN; MFG_NAME01: WURTH ELEKTRONIK EISOS GMBH & CO. KG (ELECTRONIC & ELECTROMEHANICAL COMP); MFG_PN01: 61300211121; Package Type: TH; ROHS: Yes; SILK: SWD_DIS; Temp Range: -40°C to 105°C
L11-L13 = INDUCTOR: IND FER BEAD 600OHM@100MHz 1A 25% 0603; 3D_Mechanical_Footprint_File: http://fcl.am.freescale.net/ALLEGRO/step/ind_1p8x1mm_sm.step; AGILE_PN: 180-78469; CAD_APPROVED: Yes; HEIGHT: 1; MFG_NAME01: WURTH ELEKTRONIK EISOS GMBH & CO. KG (ELECTRONIC & ELECTROMEHANICAL COMP); MFG_PN01: 742792651; ROHS: Yes
L14 = INDUCTOR: IND -- 4.7uH@1MHZ 800mA 0.23 OHM 30% 0805; 3D_Mechanical_Footprint_File: http://fcl.am.freescale.net/ALLEGRO/step/ind_0805.STEP; AGILE_PN: 180-81632; CAD_APPROVED: Yes; FPLIST: IND_0805,0805_CC; HEIGHT: 1; MFG_NAME01: MURATA; MFG_PN01: LQM21PN4R7NGRD; Package Size: 0805 (2012 metric); ROHS: Yes; Temp Range: -55°C to 125°C
L15 = INDUCTOR: IND FER BEAD 300Ohms@100MHz 2A 25% 0603; 3D_Mechanical_Footprint_File: http://fcl.am.freescale.net/ALLEGRO/step/ind_1p8x1mm_sm.step; AGILE_PN: 180-78959; CAD_APPROVED: Yes; HEIGHT: 1; MFG_NAME01: WURTH ELEKTRONIK EISOS GMBH & CO. KG (ELECTRONIC & ELECTROMEHANICAL COMP); MFG_PN01: 742792641; Package Size: 0603; ROHS: Yes; Temp Range: -55°C to 125°C
R116 R161 R162 R164 R176 R186-R188 R191 R197 = RES: RES MF 10K 1/16W 5% 0402; AGILE_PN: 470-75557; CAD_APPROVED: Yes; FPLIST: RC0402_25,RC0402_HD,0402_CC; HEIGHT: 0.4; MFG_NAME01: BOURNS; MFG_PN01: CR0402-JW-103GLF; ROHS: NULL; Tolerance: 5%
R117 = RES: RES MF 100 OHM 1/16W 5% 0402; AGILE_PN: 470-75591; CAD_APPROVED: Yes; FPLIST: RC0402_25,RC0402_HD,RC0402_X2,0402_CC; HEIGHT: 0.45; MFG_NAME01: BOURNS; MFG_PN01: CR0402-JW-101GLF; ROHS: Yes; Tolerance: 5%
R118-R120 = RES: RES 510 OHMS 1/16W 5% RC0402 ROHS; AGILE_PN: 470-76237; CAD_APPROVED: Yes; FPLIST: RC0402_25,RC0402_HD,0402_CC; HEIGHT: 0.4; MFG_NAME01: YAGEO AMERICA; MFG_PN01: RC0402JR-07510RL; ROHS: Yes; Temp_Range: -55C to +155C
R122 = RES: RES MF 20K 1/16W 5% 0402; AGILE_PN: 470-76086; ASSY_OPT: DNP; CAD_APPROVED: Yes; FPLIST: RC0402_25,RC0402_HD,0402_CC; HEIGHT: 0.4; MFG_NAME01: BOURNS; MFG_PN01: CR0402-JW-203GLF; ROHS: Yes; Tolerance: 5%
R125 R126 R148 = RES: RES MF 2.0K 1/10W 5% 0603; AGILE_PN: 470-75408; CAD_APPROVED: Yes; FPLIST: RC0603_OV,RC0603,0603_CC; HEIGHT: 0.55; MFG_NAME01: BOURNS; MFG_PN01: CR0603-JW-202ELF; ROHS: Yes; Tolerance: 5%; VOLTAGE: 1/10W
R127 R145-R147 R149 = RES: RES MF 100K 1/16W 1% 0402; AGILE_PN: 470-76240; CAD_APPROVED: Yes; FPLIST: RC0402_25,RC0402_HD,0402_CC; HEIGHT: 0.4; MFG_NAME01: NIC COMPONENTS CORP; MFG_PN01: NRCL04F1003TRF; ROHS: Yes; Tolerance: 1%
R130 R133 R134 R137 = RES: RES MF 1K 1/16W 1% AEC-Q200 0402; 3D_Mechanical_Footprint_File: http://fcl.am.freescale.net/ALLEGRO/step/rc0402_25.STEP; AGILE_PN: 470-83212; ASSY_OPT: DNP; CAD_APPROVED: Yes; FPLIST: rc0402_25,rc0402_hd,0402_cc; HEIGHT: 0.4; MFG_NAME01: STACKPOLE ELECTRONICS; MFG_PN01: RMCF0402FT1K00; Package Size: 0402 (1005 Metric); Package Type: SMD/SMT; ROHS: Yes; Temp Range: -55°C to +155°C; Tolerance: ±1%
R132 R135 R136 = RES: RES MF 1K 1/16W 1% AEC-Q200 0402; 3D_Mechanical_Footprint_File: http://fcl.am.freescale.net/ALLEGRO/step/rc0402_25.STEP; AGILE_PN: 470-83212; CAD_APPROVED: Yes; FPLIST: rc0402_25,rc0402_hd,0402_cc; HEIGHT: 0.4; MFG_NAME01: STACKPOLE ELECTRONICS; MFG_PN01: RMCF0402FT1K00; Package Size: 0402 (1005 Metric); Package Type: SMD/SMT; ROHS: Yes; Temp Range: -55°C to +155°C; Tolerance: ±1%
R213 = RES: RES MF 5.1K  1/16W 1% 0402; AGILE_PN: 470-30914; CAD_APPROVED: Yes; FPLIST: RC0402_25,RC0402_HD,0402_CC; HEIGHT: 0.40; MFG_NAME01: YAGEO AMERICA; MFG_PN01: RC0402FR-075K1L; ROHS: Yes; Tolerance: 1%
R214 = RES: RES MF 5.1K  1/16W 1% 0402; 1%: 1%; AGILE_PN: 470-30914; CAD_APPROVED: Yes; FPLIST: RC0402_25,RC0402_HD,0402_CC; HEIGHT: 0.40; MFG_NAME01: YAGEO AMERICA; MFG_PN01: RC0402FR-075K1L; ROHS: Yes; Tolerance: 1%
U8 = NIOBE4_MINI_FBGA98: IC MCU ARM FLASH 640KB SRAM 320KB 1.8-3.6V VFBGA 98; 3D_Mechanical_Footprint_File: http://fcl.am.freescale.net/ALLEGRO/step/bga98_0p5_7x7.step; AGILE_PN: 344-02410; CAD_APPROVED: Yes; FPLIST: bga98_0p5_7x7,bga98_0p5_7x7_c010s_nsp; HEIGHT: 0.97; MFG_NAME01: NXP SEMICONDUCTOR; ROHS: Yes; Supply Voltage: 1.8-3.6V; Temp Range: -40 to +105C; VOLTAGE: 1.8/3.6V
U9 = RCLAMP1654P_NEW: DIODE TVS ARRAY 3 5.5V SLP1616P6; 3D_Mechanical_Footprint_File: http://fcl.am.freescale.net/ALLEGRO/step/slp1616p6.step; AGILE_PN: 480-78843; ASSY_OPT: DNP; CAD_APPROVED: Yes; HEIGHT: 0.65; MFG_NAME01: SEMTECH CORP; ROHS: Yes; Rated Voltage: 5.5V; VOLTAGE: 5.5V
Y1 = XTAL_4P_B: XTAL 16MHz 20ppm 8pF SMT; 3D_Mechanical_Footprint_File: http://fcl.am.freescale.net/ALLEGRO/step/xtal4_3p4x2p7_sm.STEP; AGILE_PN: 230-78680; CAD_APPROVED: Yes; Frequency Tolerance: ±20ppm; HEIGHT: 0.8; MFG_NAME01: Würth Elektronik; MFG_PN01: 830064296; ROHS: Yes; Temp Range: -10.00 to 70.00°C
D9 D10 = DIODE_TVS: DIODE TVS UNIDIR 3.3VWM 20VC SOD523; AGILE_PN: 480-79814; ASSY_OPT: DNP; CAD_APPROVED: Yes; HEIGHT: 0.65; MFG_NAME01: NEXPERIA; MFG_PN01: PESD3V3S1UB,115; REQUESTED_COMPLETION_DATE: Not an expedite request; ROHS: Yes
D11 = DIODE_ARRAY_5CH: DIODE TVS UNIDIR 3.3VWM 12VC SOT363; AGILE_PN: 480-79841; ASSY_OPT: DNP; CAD_APPROVED: Yes; HEIGHT: 1.1; MFG_NAME01: NEXPERIA; MFG_PN01: PESD3V3L5UY,115; REQUESTED_COMPLETION_DATE: Not an expedite request; ROHS: Yes; Temp Range: -65°C ~ 150°C; Temp_Range: -65°C ~ 150°C
J12 = CONN_HDR_5X2: HDR 2X5 TH 50MIL CTR 167H AU 91L; AGILE_PN: 210-80192; CAD_APPROVED: Yes; FPLIST: hdr_5X2_ftsh_th,hdr_5X2_ftsh_th_nsp,hdr_5X2_ftsh_th_nsp_swd; HEIGHT: 4.25; MFG_NAME01: ANYTRONIC CORPORATION LIMITED; MFG_PN01: 0922S0205011N6T-2LF; ROHS: NULL; SILK: MCU SWD
JP8 = CONN_HDR_2X1: HDR 1X2 TH 100MIL SP 342H AU 118L; 3D_Mechanical_Footprint_File: http://fcl.am.freescale.net/ALLEGRO/step/hdr1x2_5p48x2p69.STEP; AGILE_PN: 210-80468; CAD_APPROVED: Yes; HEIGHT: 8.69; JUMPER(DEFAULT): 1-2; MFG_NAME01: WURTH ELEKTRONIK EISOS GMBH & CO. KG (ELECTRONIC & ELECTROMEHANICAL COMP); MFG_PN01: 61300211121; Package Type: TH; ROHS: Yes; SILK: SWD_CLK; Temp Range: -40°C to 105°C
R144 = RES: RES MF 100 OHM 1/16W 5% 0402; AGILE_PN: 470-75591; CAD_APPROVED: Yes; HEIGHT: 0.45; MFG_NAME01: BOURNS; MFG_PN01: CR0402-JW-101GLF; ROHS: Yes; Tolerance: 5%
R216 = RES: RES MF 220 OHM 1/10W 5% 0603; AGILE_PN: 470-30297; CAD_APPROVED: Yes; FPLIST: RC0603_OV,RC0603,0603_CC; HEIGHT: 0.6; MFG_NAME01: WALSIN TECHNOLOGY CORP.; MFG_PN01: WR06X221 JTL; ROHS: Yes; Tolerance: 5%
C86 C88 C90 = CAP_NP: CAP CER 1000PF 50V 5% C0G 0402; AGILE_PN: 150-76334; CAD_APPROVED: Yes; HEIGHT: 0.55; MFG_NAME01: MURATA; MFG_PN01: GRM1555C1H102JA01D; Package Size: 0402; Package Type: 180mm Paper Tape; ROHS: Yes; Rated Voltage: 50V; Temp Range: -55C to +125C; Tolerance: 5%
C87 = CAP_NP: CAP CER 0.1UF 16V 10% X7R 0402; 3D_Mechanical_Footprint_File: http://fcl.am.freescale.net/ALLEGRO/step/cc0402_25.STEP; AGILE_PN: 150-75182; ASSY_OPT: DNP; CAD_APPROVED: Yes; FPLIST: CC0402_25,CC0402_HD,0402_CC,CAPC0402_L; HEIGHT: 0.635; MFG_NAME01: Samsung Electro-Mechanics; MFG_PN01: CL05B104KO5NNNC; ROHS: Yes; Rated Voltage: 16V; Temp Range: -55C to +125C; Tolerance: 10%; VOLTAGE: 16V
C94 C95 = CAP_NP: CAP CER 12PF 25V 5% C0G 0402; AGILE_PN: 150-30180; ASSY_OPT: DNP; CAD_APPROVED: Yes; HEIGHT: 0.55; MFG_NAME01: KEMET; MFG_PN01: C0402C120J3GAC7867; ROHS: Yes; Rated Voltage: 25V; Temp Range: -55C to +125C; Tolerance: 5%
C96 C97 = CAP_NP: CAP CER 4.7PF 50V 0.25PF C0G 0402; AGILE_PN: 150-76335; CAD_APPROVED: Yes; FPLIST: CC0402_25,CC0402_HD,0402_CC; HEIGHT: 0.56; MFG_NAME01: AVX; MFG_PN01: 04025A4R7CAT2A; ROHS: Yes; Rated Voltage: 50V; Temp Range: -55C to +125C; Tolerance: 0.25pF; VOLTAGE: 50V
D12 = LED: LED RED SGL 20MA 0603; AGILE_PN: 370-76632; CAD_APPROVED: Yes; HEIGHT: 0.45; MFG_NAME01: LITE ON; MFG_PN01: LTST-C193KRKT-5A; ROHS: Yes; SILK: RESET
D13 = LRTBR48G_4P: LED RED/GRN/BL TRI 20/20/20MA SMT; AGILE_PN: 370-76899; CAD_APPROVED: YES; HEIGHT: 2.14; MFG_NAME01: Lianyungang Meihua Electronics Technology Co.,Ltd; MFG_PN01: MHPA2525RGBDT-S; Temp Range: -40 to +100
R163 R168 R169 = RES: RES MF 470 OHM 1/16W 1% 0402; AGILE_PN: 470-76469; CAD_APPROVED: Yes; FPLIST: RC0402_25,RC0402_HD,0402_CC; HEIGHT: 0.4; MFG_NAME01: THYE MING TECH CO LTD; MFG_PN01: CR-02FL6--470R; ROHS: Yes; SIGNAL_MODEL: DEFAULT_RESISTOR_430.000000OHM_2_1; TOL: 1%; Temp_Range: -55&#8451; to 155&#8451;; Tolerance: 1%; VOLTAGE: 50V
R167 = RES: RES MF 680 OHM 1/10W 1% 0603; AGILE_PN: 470-30384; CAD_APPROVED: Yes; FPLIST: RC0603_OV,RC0603,0603_CC; HEIGHT: 0.55; MFG_NAME01: BOURNS; MFG_PN01: CR0603-FX-6800ELF; ROHS: Yes; Tolerance: 1%
R170 = RES: RES MF 1M 1/10W 5% AEC-Q200 0402; AGILE_PN: 470-79978; ASSY_OPT: DNP; CAD_APPROVED: Yes; FPLIST: RC0402_25,RC0402_HD,0402_CC; HEIGHT: 0.4; MFG_NAME01: KOA SPEER; MFG_PN01: RK73B1ETTP105J; ROHS: Yes; Temp Range: -55&#8451; to 155&#8451;; Temp_Range: -55&#8451; to 155&#8451;; Tolerance: 5%; VOLTAGE: 50V
SW1 = SW_PSHBT_SPST_2: SW SP PB 50mA 16V SMT; 3D_Mechanical_Footprint_File: http://fcl.am.freescale.net/ALLEGRO/step/sw4_4p15_4p2x3p2_sm.STEP; AGILE_PN: 510-78653; CAD_APPROVED: Yes; HEIGHT: 2.60; MFG_NAME01: WURTH ELEKTRONIK EISOS GMBH & CO. KG (ELECTRONIC & ELECTROMEHANICAL COMP); MFG_PN01: 434123025826; ROHS: Yes; SILK: RESET; Temp Range: -40C to +85C
SW2 = SW_PSHBT_SPST_2: SW SP PB 50mA 16V SMT; 3D_Mechanical_Footprint_File: http://fcl.am.freescale.net/ALLEGRO/step/sw4_4p15_4p2x3p2_sm.STEP; AGILE_PN: 510-78653; CAD_APPROVED: Yes; HEIGHT: 2.60; MFG_NAME01: WURTH ELEKTRONIK EISOS GMBH & CO. KG (ELECTRONIC & ELECTROMEHANICAL COMP); MFG_PN01: 434123025826; ROHS: Yes; SILK: WAKEUP; Temp Range: -40C to +85C
SW3 = SW_PSHBT_SPST_2: SW SP PB 50mA 16V SMT; 3D_Mechanical_Footprint_File: http://fcl.am.freescale.net/ALLEGRO/step/sw4_4p15_4p2x3p2_sm.STEP; AGILE_PN: 510-78653; CAD_APPROVED: Yes; HEIGHT: 2.60; MFG_NAME01: WURTH ELEKTRONIK EISOS GMBH & CO. KG (ELECTRONIC & ELECTROMEHANICAL COMP); MFG_PN01: 434123025826; ROHS: Yes; SILK: ISP; Temp Range: -40C to +85C
Y2 = CRYSTAL: XTAL 32.768kHz 12.5pF 1.05pF 20ppm SMT; 3D_Mechanical_Footprint_File: http://fcl.am.freescale.net/ALLEGRO/step/xtal2-3p2x1p5-sm.step; AGILE_PN: 230-78676; CAD_APPROVED: Yes; HEIGHT: 0.9; MFG_NAME01: Wurth Electronics Inc.; MFG_PN01: 830009678; ROHS: Yes
Y3 = XTAL_4PIN: XTAL 24MHz 10ppm 8pF SMT; 3D_Mechanical_Footprint_File: http://fcl.am.freescale.net/ALLEGRO/step/xtal4_2p1x1p7mm_sm.STEP; AGILE_PN: 230-78677; CAD_APPROVED: YES; Frequency Tolerance: ±10ppm; HEIGHT: 0.50; MFG_NAME01: Wurth Electronics Inc.; MFG_PN01: 830108212309; ROHS: Yes; Temp Range: -40°C to +85°C
C100 = CAP_NP: CAP CER 0.1UF 16V 10% X7R 0402; 3D_Mechanical_Footprint_File: http://fcl.am.freescale.net/ALLEGRO/step/cc0402_25.STEP; AGILE_PN: 150-75182; ASSY_OPT: DNP; CAD_APPROVED: Yes; FPLIST: CC0402_25,CC0402_HD,0402_CC,CAPC0402_L; HEIGHT: 0.635; MFG_NAME01: Samsung Electro-Mechanics; MFG_PN01: CL05B104KO5NNNC; ROHS: Yes; Rated Voltage: 16V; TOL: 10%; Temp Range: -55C to +125C; Tolerance: 10%; VOLTAGE: 16V
C104 C108 = CAP_NP: CAP CER 56PF 50V 5% C0G 0402; AGILE_PN: 150-30269; CAD_APPROVED: Yes; FPLIST: CC0402_25,CC0402_HD,0402_CC; HEIGHT: 0.55; MFG_NAME01: VENKEL COMPANY; MFG_PN01: C0402C0G500-560JNE; ROHS: Yes; Rated Voltage: 50V; Temp Range: -55C to +125C; Tolerance: 5%; VOLTAGE: 50V
C105 = CAP_NP: CAP CER 0.01UF 25V 10% X8R 0402; AGILE_PN: 150-77996; ASSY_OPT: DNP; CAD_APPROVED: Yes; FPLIST: CC0402_25,CC0402_HD,0402_CC,capc0402_l; HEIGHT: 0.55; MFG_NAME01: TDK; MFG_PN01: C1005X8R1E103K050BA; ROHS: Yes; Rated Voltage: 25V; TOL: 20%; Temp Range: -55C to +150C; Tolerance: 10%; VOLTAGE: 25V
C107 = CAP_NP: CAP CER 0.1UF 16V 10% X7R 0402; 3D_Mechanical_Footprint_File: http://fcl.am.freescale.net/ALLEGRO/step/cc0402_25.STEP; AGILE_PN: 150-75182; CAD_APPROVED: Yes; FPLIST: CC0402_25,CC0402_HD,0402_CC,CAPC0402_L; HEIGHT: 0.635; MFG_NAME01: Samsung Electro-Mechanics; MFG_PN01: CL05B104KO5NNNC; ROHS: Yes; Rated Voltage: 16V; SIGNAL_MODEL: DEFAULT_CAPACITOR_100000pF_2_1; TOL: 10%; Temp Range: -55C to +125C; Tolerance: 10%; VOLTAGE: 16V
D14 = DIODE_NUP2105L: DIODE DUAL LINE CAN BUS PROTECTOR 27V 350W SOT-23; AGILE_PN: 480-77157; CAD_APPROVED: Yes; HEIGHT: 1.11; MFG_NAME01: ON SEMICONDUCTOR; MFG_PN01: NUP2105LT1G; ROHS: Yes
J13 = CONN_HDR_2X2: HDR 2X2 TH 100MIL CTR 340H SN 105L; AGILE_PN: 210-78429; CAD_APPROVED: Yes; HEIGHT: 8.9; MFG_NAME01: TYCO ELECTRONICS; MFG_PN01: 5-146258-2; ROHS: Yes
Q2 = PT12_PHTRANS_2P: TRAN NPN PHOTO 2.5-5.5V 630NM SMT; 3D_Mechanical_Footprint_File: http://fcl.am.freescale.net/ALLEGRO/step/phtrans_1p9x1.STEP; AGILE_PN: 480-78363; CAD_APPROVED: Yes; HEIGHT: 0.7; MFG_NAME01: EVERLIGHT INTERNATIONAL CORPORATION; ROHS: Yes; VOLTAGE: 2.5-5.5V
R173 R174 = RES: RES MF 4.7K OHM 1/16W 1% 0402; AGILE_PN: 470-80911; CAD_APPROVED: Yes; FPLIST: RC0402_25,RC0402_HD,0402_CC; HEIGHT: 0.4; MFG_NAME01: YAGEO; MFG_PN01: RC0402FR-074K7L; ROHS: Yes; Tolerance: 1%
R175 R181 = RES: RES MF 10K 1/16W 5% 0402; AGILE_PN: 470-75557; ASSY_OPT: DNP; CAD_APPROVED: Yes; FPLIST: RC0402_25,RC0402_HD,0402_CC; HEIGHT: 0.4; MFG_NAME01: BOURNS; MFG_PN01: CR0402-JW-103GLF; ROHS: NULL; Tolerance: 5%
R178 = RES: RES MF 15.0K 1/16W 1% 0402; AGILE_PN: 470-76066; CAD_APPROVED: Yes; FPLIST: RC0402_25,RC0402_HD,0402_CC; HEIGHT: 0.4; MFG_NAME01: BOURNS; MFG_PN01: CR0402-FX-1502GLF; ROHS: Yes; Tolerance: 1%
R184 R189 = RES: RES MF 62 OHM 1/4W 5% AEC-Q200 0805; AGILE_PN: 470-82103; CAD_APPROVED: Yes; FPLIST: RC0805_OV,RC0805,0805_CC; HEIGHT: 0.7; MFG_NAME01: KOA SPEER; MFG_PN01: RK73B2ATTD620J; ROHS: Yes; Temp Range: -55C to +155C; Tolerance: 5%
R185 = RES: RES MF 100K 1/16W 1% 0402; AGILE_PN: 470-76240; CAD_APPROVED: Yes; FPLIST: RC0402_25,RC0402_HD,0402_CC; HEIGHT: 0.4; MFG_NAME01: NIC COMPONENTS CORP; MFG_PN01: NRCL04F1003TRF; ROHS: Yes; TOL: 5%; Temp_Range: -55C to +155C; Tolerance: 1%
R202 = RES: RES MF 100K 1/16W 1% 0402; AGILE_PN: 470-76240; ASSY_OPT: DNP; CAD_APPROVED: Yes; FPLIST: RC0402_25,RC0402_HD,0402_CC; HEIGHT: 0.4; MFG_NAME01: NIC COMPONENTS CORP; MFG_PN01: NRCL04F1003TRF; ROHS: Yes; Tolerance: 1%
U10 = FXLS8962AF_DFN10: IC ACCELEROMETER 3-AXIS 12BIT 1.71-3.6V AEC-Q100 DFN10; 3D_Mechanical_Footprint_File: http://fcl.am.freescale.net/ALLEGRO/step/dfn_10_0p4_2x2.STEP; AGILE_PN: TMP-CIP-7425; CAD_APPROVED: Yes; HEIGHT: 1 MM; MFG_NAME01: NXP SEMICONDUCTORS; PRE_APN: 312-83141; ROHS: Yes; Temp Range: -40  °C to +105 °C
U11 = TJA1051TK_3_HVSON8: IC XCVR CAN 5MBIT/S 4.75-5.25V AEC-Q100 HVSON8; 3D_Mechanical_Footprint_File: http://fcl.am.freescale.net/ALLEGRO/step/son8_0p65_3p15x3p15.STEP; AGILE_PN: 312-83230; CAD_APPROVED: Yes; HEIGHT: 1; MFG_NAME01: NXP Semiconductors; Package Size: HVSON-8; ROHS: Yes; Supply Voltage: 4.75 V to 5.25 V; Temp Range: -40 °C to +150 °C
U12 = W25Q64JV_SOIC_8P_B: IC MEM SERIAL FLASH DUAL/QUAD SPI 64MBIT 2.7-3.6V SOIC8; AGILE_PN: 342-00710; CAD_APPROVED: Yes; HEIGHT: 2.16; MFG_NAME01: WINBOND ELECTRONICS CORP; ROHS: Yes; Temp Range: ¨C40C to +85C; VOLTAGE: 2.7-3.6V

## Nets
GND: C42.2 C43.2 C44.2 C45.2 C46.2 C47.2 C48.2 C49.2 C50.2 C51.2 C53.2 C54.2 C55.2 C58.1 C59.2 C60.2 C62.2 C63.2 C64.2 C65.2 C66.2 C67.2 C68.2 C69.2 C70.2 C71.2 C72.2 C73.2 C74.2 C75.2 C76.2 C77.2 C78.2 C79.2 C80.2 C81.2 C82.2 C83.2 C85.2 C86.2 C87.2 C88.2 C90.2 C94.2 C95.2 C96.2 C97.2 C98.2 C99.2 C100.2 C101.2 C102.2 C103.2 C104.1 C105.2 C106.2 C107.2 C108.2 D9.A D10.A D11.2(A) D14.3(ANODES) J10.A1(GND1) J10.A12(GND2) J10.B1(GND4) J10.B12(GND3) J10.SH1 J10.SH2 J10.SH3 J10.SH4 J12.3(A2) J12.5(A3) J13.3(A2) J21.1 J21.2 JP5.1 JP6.1 JP7.1 R100.1 R111.1 R112.1 R113.2 R122.2 R126.2 R130.2 R132.2 R133.2 R134.2 R135.2 R136.2 R137.2 R149.2 R150.2 R176.1 R178.2 R185.2 R191.2 R197.1 R204.1 R213.2 R214.2 SW1.1 SW1.2 SW2.1 SW2.2 SW3.1 SW3.2 U6.B2(GND_CP) U6.B10(GND_A) U7.5(GND1) U7.6(GND2) U7.7(GND3) U7.8(GND4) U8.B1(USB0_VSS) U8.B5(VSS2) U8.B9(VSS3) U8.B13(VSS4) U8.H1(VREFN) U8.H2(VSSA) U8.J13(XTAL32K_P) U8.M11(VSS_PMU) U8.M12(VSS_DCDC_2) U8.N1(VSS1) U8.N5(USB1_VSS) U8.N12(VSS_DCDC_1) U9.7(GND) U10.10(GND) U11.2(GND) U11.9(EPAD) U12.4(GND) Y1.2 Y1.4 Y3.2(GND1) Y3.4(GND2) ; also on sheet 5 6 12
P5V0: R179.1 R182.2 ; also on sheet 5 6 12
P5V_MCU_LINK_USB: L15.2 R121.1 TP13.1(Pin1) ; also on sheet 5
VBAT_DCDC/VBAT_PMU: C75.1 C76.1 C77.1 L13.2 TP17.1(Pin1) U8.M13(VBAT_PMU) U8.N13(VBAT_DCDC)
VDD_1V8: C42.1 U6.B6(VDD_A) ; also on sheet 5
VDD_ACCL: C98.1 C99.1 R171.2 R173.1 R174.1 R175.2 R202.1 TP23.1(Pin1) U10.1(VDD)
VDD_AUDIO: C44.1 C45.1 C62.1 R95.2 R203.1 TP18.1(Pin1) U6.B14(VDD_MIC) U6.D10(VDD_IO) U7.4(VDD)
VDD_BOARD: C63.1 C85.1 C106.1 C107.1 L11.1 L12.1 L13.1 R95.1 R118.1 R119.1 R120.1 R125.1 R127.1 R144.1 R145.1 R146.1 R147.1 R157.1 R158.1 R161.1 R162.1 R163.1 R164.1 R166.1 R171.1 R172.2 R180.2 R186.1 R187.1 R188.1 U12.8(VCC) ; also on sheet 3 4 5 6 12
AUX_L: C57.2 U6.C13(AUX_L)
AUX_R: C56.2 U6.D14(AUX_R)
CAN1_H: C104.2 D14.2(CATHODE2) J13.2(B1) R183.1 R184.1
CAN1_H_R: R183.2 U11.7(CANH)
CAN1_L: C108.1 D14.1(CATHODE1) J13.4(B2) R189.2 R190.1
CAN1_L_R: R190.2 U11.6(CANL)
CAN_VIO_3V3: C101.1 R180.1 R181.1 TP22.1(Pin1) U11.5(VIO)
DBGIF_DETECT: R148.1 U8.E9(P0_22)
DBGIF_ISP0_CTRL: R141.1 U8.C13(P0_14)
DBGIF_RESET: R140.1 U8.E6(P0_19)
DBGIF_TCK_SWCLK: JP8.1 U8.L12(P0_0)
DBGIF_TDI: R143.1 U8.F5(P0_1)
DBGIF_TDO_SWO: R142.1 U8.F8(P0_3)
DBGIF_TMS_SWDIO: R139.1 U8.B11(P0_2)
DBGIF_VREF: C83.1 R125.2 R126.1 TP10.1(Pin1) U8.L1(P0_31)
HP_L: C49.1 L7.2 U6.A3(HP_L)
HP_R: C46.1 L6.2 U6.A5(HP_R)
HP_S: R97.2 R98.1 R100.2 U6.B4(GND_SENSE)
HS_1: J14.1 R98.2 R102.2
HS_2: J14.2 R97.1 R101.1
HS_USB1_DM: J10.A7(DN1) J10.B7(DN2) U8.N6(USB1_DM) U9.1(DM)
HS_USB1_DP: J10.A6(DP1) J10.B6(DP2) U8.M6(USB1_DP) U9.2(DP)
HW_VER_0: R130.1 U8.E8(P1_27)
HW_VER_1: R133.1 U8.A8(P1_28)
HW_VER_2: R134.1 U8.F9(P1_30)
HW_VER_3: R135.1 U8.B2(P1_4)
HW_VER_4: R136.1 U8.M5(P1_5)
HW_VER_5: R137.1 U8.H5(P1_6)
HW_VER_6: JP6.2 U8.H9(P0_18)
HW_VER_7: JP7.2 U8.N2(P0_27)
HW_VER_8: R132.1 U8.L13(P0_9)
JTAG_VREF: J12.1(A1) R144.2
LED_USB_COMM: D6.C(CATHODE) U8.F12(P1_12)
LED_VCOM_ACT: D8.C(CATHODE) U8.B6(P1_15)
MCU_LINK_3V3: C64.1 C65.1 C66.1 C67.1 C68.1 C80.1 C81.1 L11.2 R116.1 TP12.1(Pin1) U8.A3(USB0_3V3) U8.A5(VDD2) U8.A9(VDD3) U8.A13(VDD4) U8.M1(VDD1) U8.N7(USB1_3V3)
MCU_LINK_I2C0_SCL: R157.2 R159.2 U8.A12(P0_21)
MCU_LINK_I2C0_SDA: R158.2 R160.2 U8.E7(P0_4)
MCU_LINK_N_16MHz: C78.1 U8.M3(XTAL32M_N) Y1.3
MCU_LINK_P_16MHz: C79.1 U8.N3(XTAL32M_P) Y1.1
MCU_LINK_RST: R117.2 U8.J6(RESETN)
MCU_LINK_RX: U8.E12(P0_24) ; also on sheet 4
MCU_LINK_SPI1_MISO: R156.2 U8.G13(P1_3)
MCU_LINK_SPI1_MOSI: R154.2 U8.H12(P0_26)
MCU_LINK_SPI1_SCLK: R153.2 U8.G12(P1_2)
MCU_LINK_SPI1_SSEL: R155.2 U8.B12(P0_20)
MCU_LINK_TX: R216.2 U8.A11(P0_25)
MCU_RESET_B: C86.1 C87.1 D11.1(K1) D12.C(CATHODE) J12.10(B5) R140.2 R147.2 R161.2 SW1.3 SW1.4 ; also on sheet 4 12
MCU_UART_RX: R216.1 ; also on sheet 4
MIC2_R: C61.2 TP6.1(Pin1) U6.D16(MIC2_P)
MIC_HDST: C54.1 C61.1 L8.2 R110.2 R113.1
MICBIAS1: C50.1 U6.A15(MICBIAS1)
MICBIAS2: C53.1 R110.1 U6.A17(MICBIAS2)
P0_0/SWDIO: D11.6(K5) J12.2(B1) R139.2 R145.2 ; also on sheet 3
P0_1/SWCLK: D11.5(K4) J12.4(B2) JP8.2 R149.1 ; also on sheet 3
P0_2/SWO: D11.4(K3) J12.6(B3) R142.2 ; also on sheet 3
P0_3/TDI: D11.3(K2) J12.8(B4) R143.2 R146.2 ; also on sheet 3
P0_6: D9.C J12.7(A4) R141.2 ; also on sheet 3
P0_6/ISPMODE_N-SW: C88.1 R162.2 SW3.3 SW3.4 ; also on sheet 3
P0_16: R160.1 ; also on sheet 3
P0_16/PDM0_CLK-DMIC: R96.1 U7.2(CLK) ; also on sheet 3 12
P0_17: R159.1 ; also on sheet 3
P0_17/PDM0_DATA0-DMIC: R99.1 U7.1(DAT) ; also on sheet 3 12
P0_20/WUU0_IN4-SW: C90.1 R164.2 SW2.3 SW2.4 ; also on sheet 3
P0_21/ACCL_INT1: R173.2 U10.8(INT1/MOT_DET) ; also on sheet 3
P0_23/ACCL_WAKEUP: U10.7(~{SPI_CS}/WAKE_UP) ; also on sheet 3
P0_24/ACCL_INT2: R174.2 U10.6(INT2/EXT_TRIG/BOOT_OUT) ; also on sheet 3
P0_25/ADC0_B17-LIGHT_SENSOR: R38.2 ; also on sheet 3 12
P1_0: R156.1 ; also on sheet 3 12
P1_1: R153.1 ; also on sheet 3 12
P1_2: R154.1 ; also on sheet 3 12
P1_3: R155.1 ; also on sheet 3 12
P1_30/XTAL48M: C96.1 R170.1 Y3.1 ; also on sheet 3
P1_31/EXTAL48M: C97.1 R170.2 Y3.3 ; also on sheet 3
P2_8/SAI1_TXD0: R109.1 ; also on sheet 3 12
P2_9/SAI1_RXD0: R107.1 ; also on sheet 3 12
P3_6/SAI1_MCLK: R103.2 ; also on sheet 3 12
P3_12/FC6_QSPI_D3: R186.2 U12.7(IO3) ; also on sheet 3
P3_13/FC6_QSPI_D2: R188.2 U12.3(IO2) ; also on sheet 3
P3_16: R106.1 ; also on sheet 3 12
P3_17: R108.1 ; also on sheet 3 12
P3_20/FC6_QSPI_D0: U12.5(DI/IO0) ; also on sheet 3
P3_21/FC6_QSPI_SCK: U12.6(CLK) ; also on sheet 3
P3_22/FC6_QSPI_D1: U12.2(DO/IO1) ; also on sheet 3
P3_23/FC6_QSPI_CS0: R187.2 U12.1(~{CS}) ; also on sheet 3
P4_0: R105.1 ; also on sheet 4 6 12
P4_0/FC2_I2C_SDA-ACCL: U10.4(SDA/SPI_MOSI/SPI_DATA) ; also on sheet 4
P4_1: R104.1 ; also on sheet 4 6 12
P4_1/FC2_I2C_SCL-ACCL: U10.5(SCL/SCLK) ; also on sheet 4
P4_15/CAN1_RXD: U11.4(RXD) ; also on sheet 4
P4_16/CAN1_TXD: U11.1(TXD) ; also on sheet 4
P4_17: R169.2 ; also on sheet 4 6 12
P4_18: R167.2 ; also on sheet 4 12
P4_19: R168.2 ; also on sheet 4 12
P5_0/EXTAL32K: C95.1 Y2.2 ; also on sheet 4
P5_1/XTAL32K: C94.1 Y2.1 ; also on sheet 4
PIO0_5-ISP_EN-LED_SWD_ACT: D7.C(CATHODE) JP5.2 R127.2 U8.A7(P0_5)
SNS_LIGHT_ADC: C100.1 Q2.2(EMITTER) R38.1 R178.1
VDIG: C47.1 U6.D12(VDIG)
VREF_MCULINK: C70.1 C71.1 L12.2 TP21.1(Pin1) U8.G1(VREFP) U8.G2(VDDA)
N84836: C69.1 R116.2 R117.1
N85250: D6.A(ANODE) R118.2
N85474: D7.A(ANODE) R119.2
N85648: C72.1 C73.1 C74.1 L14.2 U8.M9(VDD_PMU) U8.N9(FB)
N85680: D8.A(ANODE) R120.2
N85830: L14.1 U8.N11(LX)
N87448: R121.2 R122.1 U8.N8(USB1_VBUS)
N301213: D10.C J12.9(A5) R148.2 R150.1
N383974: D13.3(CATHODE2) R168.1
N384008: D13.4(CATHODE3) R169.1
N384038: D13.2(CATHODE1) R167.1
N479793: D13.1(ANODE) R166.2
N629677: D12.A(ANODE) R163.2
N1493095: C102.1 C103.1 R179.2 U11.3(VCC)
N1493367: R181.2 R185.1 U11.8(S)
N1493767: J13.1(A1) R182.1
N1493931: C105.1 R184.2 R189.1
N16872370: C43.1 U6.A9(VMID)
N16872454: C48.1 U6.B8(VREF)
N16872595: C51.1 U6.A1(HPCSP)
N16872621: C52.1 U6.D2(HPCFP)
N16872663: C52.2 U6.C3(HPCFN)
N16872673: R103.1 U6.C11(MCLK)
N16872680: C55.1 U6.C1(HPCSN)
N16872761: TP9.1(Pin1) U6.A13(SP_N)
N16872798: C58.2 U6.A7(DACREF)
N16873720: L8.1 R101.2 R102.1
N16874336: J14.4 J14.5 L7.1
N16879603: R203.2 R204.2 U7.3(SEL)
N16880000: C56.1 C59.1 L9.2 R111.2
N16880011: C57.1 C60.1 L10.2 R112.2
N16886184: R96.2 U6.C17(MIC1_P/DMICCLK)
N16886191: R99.2 U6.B16(MIC1_N/DMICIN)
N16886584: R106.2 U6.D4(BCLK)
N16886590: R107.2 U6.C7(DATOUT)
N16886596: R108.2 U6.D6(WCLK)
N16886605: R109.2 U6.C5(DATIN)
N16887090: R105.2 U6.C9(SDA)
N16887102: R104.2 U6.D8(SCL)
N16921653: J14.3 L6.1
N16921845: J21.3 L9.1
N16921915: J21.4 J21.5 L10.1
N17029289: R191.1 R202.2 U10.3(SA0/SPI_MISO)
N17030310: R175.1 R176.2 U10.2(BT_MODE)
N17030790: R197.2 U10.9(INTF_SEL)
N17592677: C82.1 J10.A4(VBUS1) J10.A9(VBUS2) J10.B4(VBUS4) J10.B9(VBUS3) L15.1 U9.6(VBUS)
N17592697: J10.A5(CC1) R214.1
N17592749: J10.B5(CC2) R213.1
N18143667: Q2.1(COLLECTOR) R172.1
N18144611: TP8.1(Pin1) U6.B12(SP_P)
N18144613: TP5.1(Pin1) U6.A11(VDD_SP)

Not connected (* = marked no-connect by the designer): J10 A8(SBU1)* B8(SBU2)*; U6 C15(MIC2_N)*; U8 A1(USB_DM)* A2(USB_DP)* A6(P1_8)* B3(P1_13)* B7(P0_6)* B8(P1_25)* C1(P1_9)* C2(P1_20)* C7(P1_16)* C12(P0_13)* E1(P1_0)* E2(P0_12)* E5(P0_30)* E13(P1_26)* F1(P0_11)* F2(P0_10)* F6(P1_24)* F13(P0_28)* G3(P0_17)* G5(P0_7)* G6(P1_11)* G8(P1_29)* G9(P1_18)* G11(P1_1)* H6(P1_31)* H8(P0_29)* H13(P1_19)* J1(P0_23)* J2(P0_16)* J5(P1_7)* J7(P1_10)* J8(P1_23)* J9(P1_17)* J12(XTAL32K_N)* L2(P0_15)* L7(P1_14)* M2(P0_8)* M7(P1_21)* M8(P1_22)*; U9 3(USB_ID)* 4(NC1)* 5(NC2)*

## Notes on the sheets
sheet 7
- AUDIO CODEC
- Default : L/R/GND/MIC
  Populate R98, R101, DNP R97, R102 : L/R/MIC/GND
- Address: I2C address for the codec is 0x1A.
- DIGITAL MIC
sheet 8
- MCU-Link Powering and USB
- MCU-Link LEDs
- CAD note: Place 0.1 uF close to each VDD pin
- USB Communication
- Status / SWD Activity
- VCOM Activity
- L14: LQM21PN4R7NGRD
- Note:
  Place 100nF and 47pF caps
  close to Pin M13, N13
- Place C72 & C73
  close to Pin M9
- MCU-Link
- USB Typc-C
- CAD note: 90Ohms differential impedance
- Note:
  Open  : Boot from Internal Flash
  Closed: Enable ISP mode (USB1)
- HW_VER_0: USB power negotiation enable when low
  HW_VER_2: USB-SIO bridge disable when low
  HW_VER_3: OB selection when low
  HW_VER_4: Board identity code used when low
  HW_VER_5: Power measurement disable if leave open
  HW_VER_6: VCOM disable when low
  HW_VER_7: SWD disable when low
  HW_VER_8: Secondary VCOM disable when low
sheet 9
- MCU-Link Debug Interface
- External Debugger
- SWDIO/TMS
- SWDCLK/TCK
- SWO/TDO
- TDI
- nRST
- MCU VCOM
- USB Bridge
sheet 10
- PUSH BUTTON
- RESET
- ISP
- CAD note:
  Place 1000pf cap close to switch
  Place 0.1uf  cap close to Reset pin
- CAD note:
  Place cap close to switch
- WAKE UP
- CAD note:
  Place cap close to switch
- Clock
- RGB LED
- ESR=100OHM, +-15PPM, CL=8PF, -40~85C
  C96=C97=4.7pF.
sheet 11
- SENSOR & CAN & QSPI
- I2C Sensor
- Ambient Light Sensor
- ADC/LIGHT SENSOR
- SA0        8-bit I2C write address     8-bit I2C read address
  SA0: 0              30h                        31h
  SA0: 1              32h                        33h
- FlexCAN
- QSPI FLASH
- MAX 70 mA @5V
- Standby: 5 uA
